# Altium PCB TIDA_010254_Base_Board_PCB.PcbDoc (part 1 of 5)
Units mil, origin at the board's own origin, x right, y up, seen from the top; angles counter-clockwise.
Board outline 3514.38 x 3143.81 mil, 4 copper layers (Top Layer, L2_GND1, L3_PWR1, Bottom Layer), stack 62.715 mil thick; 219 components, 146 nets, 618 pads, 2382 vias.
Unrouted connection lines stored in the file: 2280.
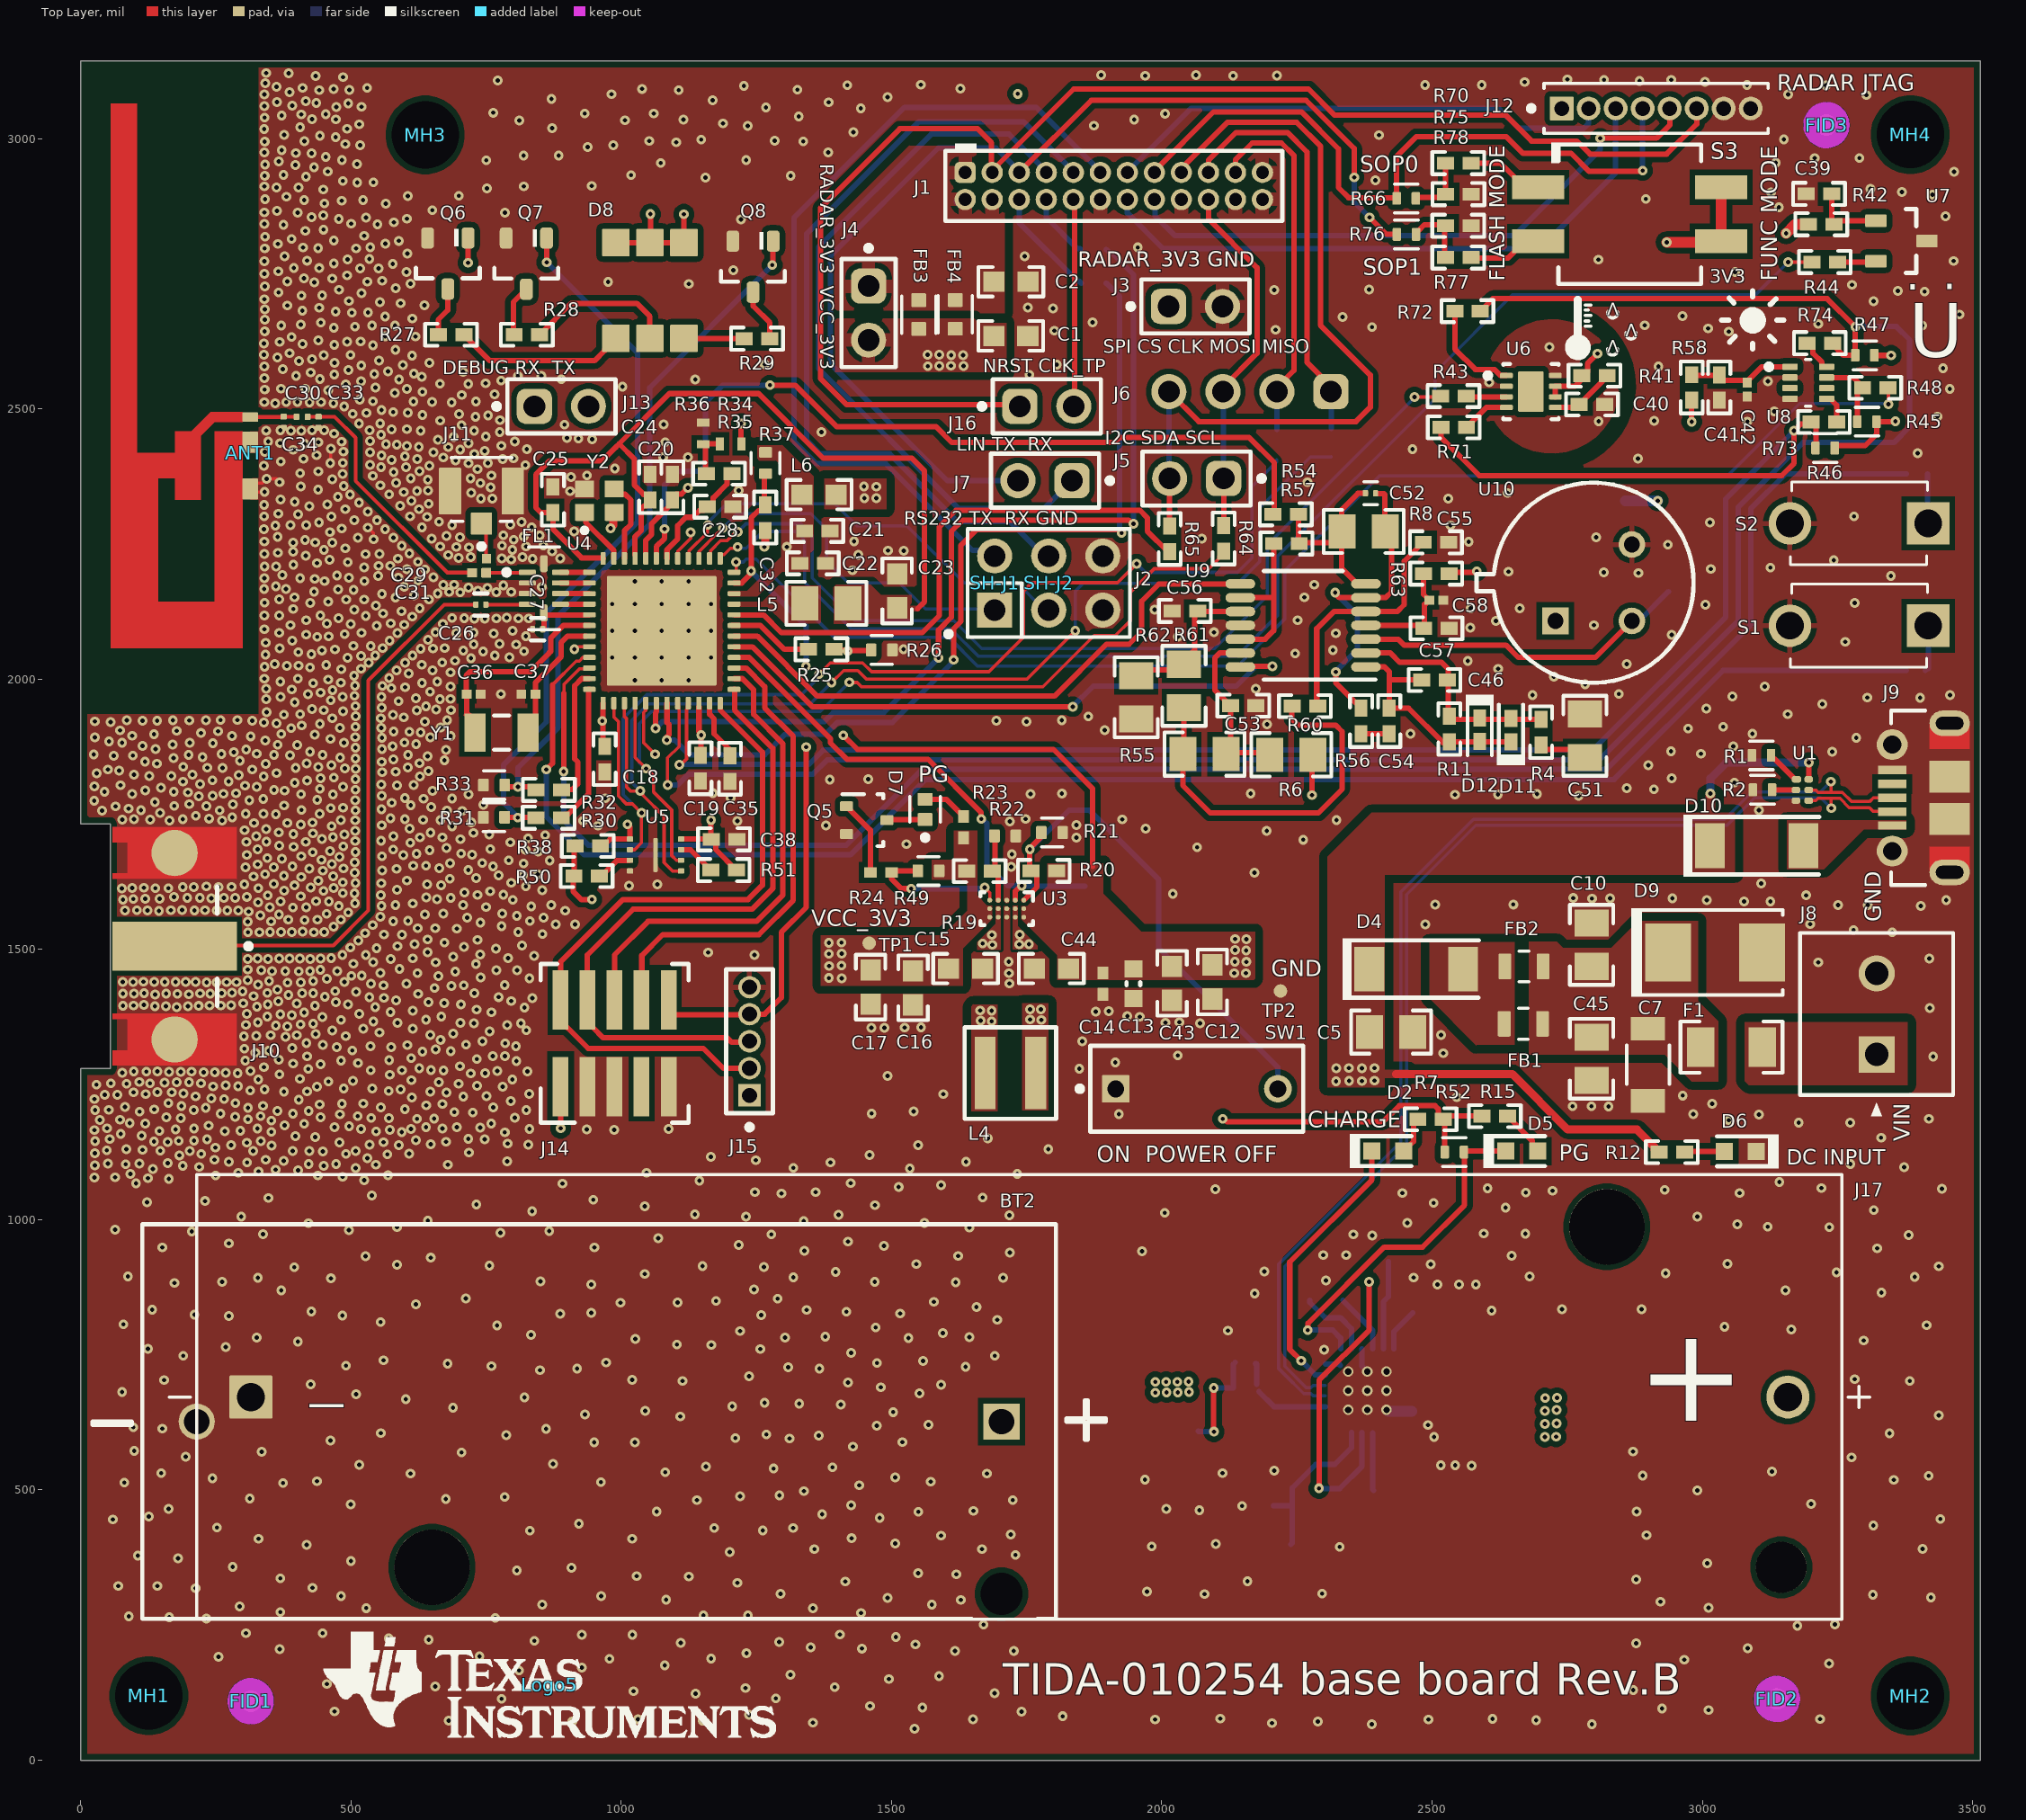
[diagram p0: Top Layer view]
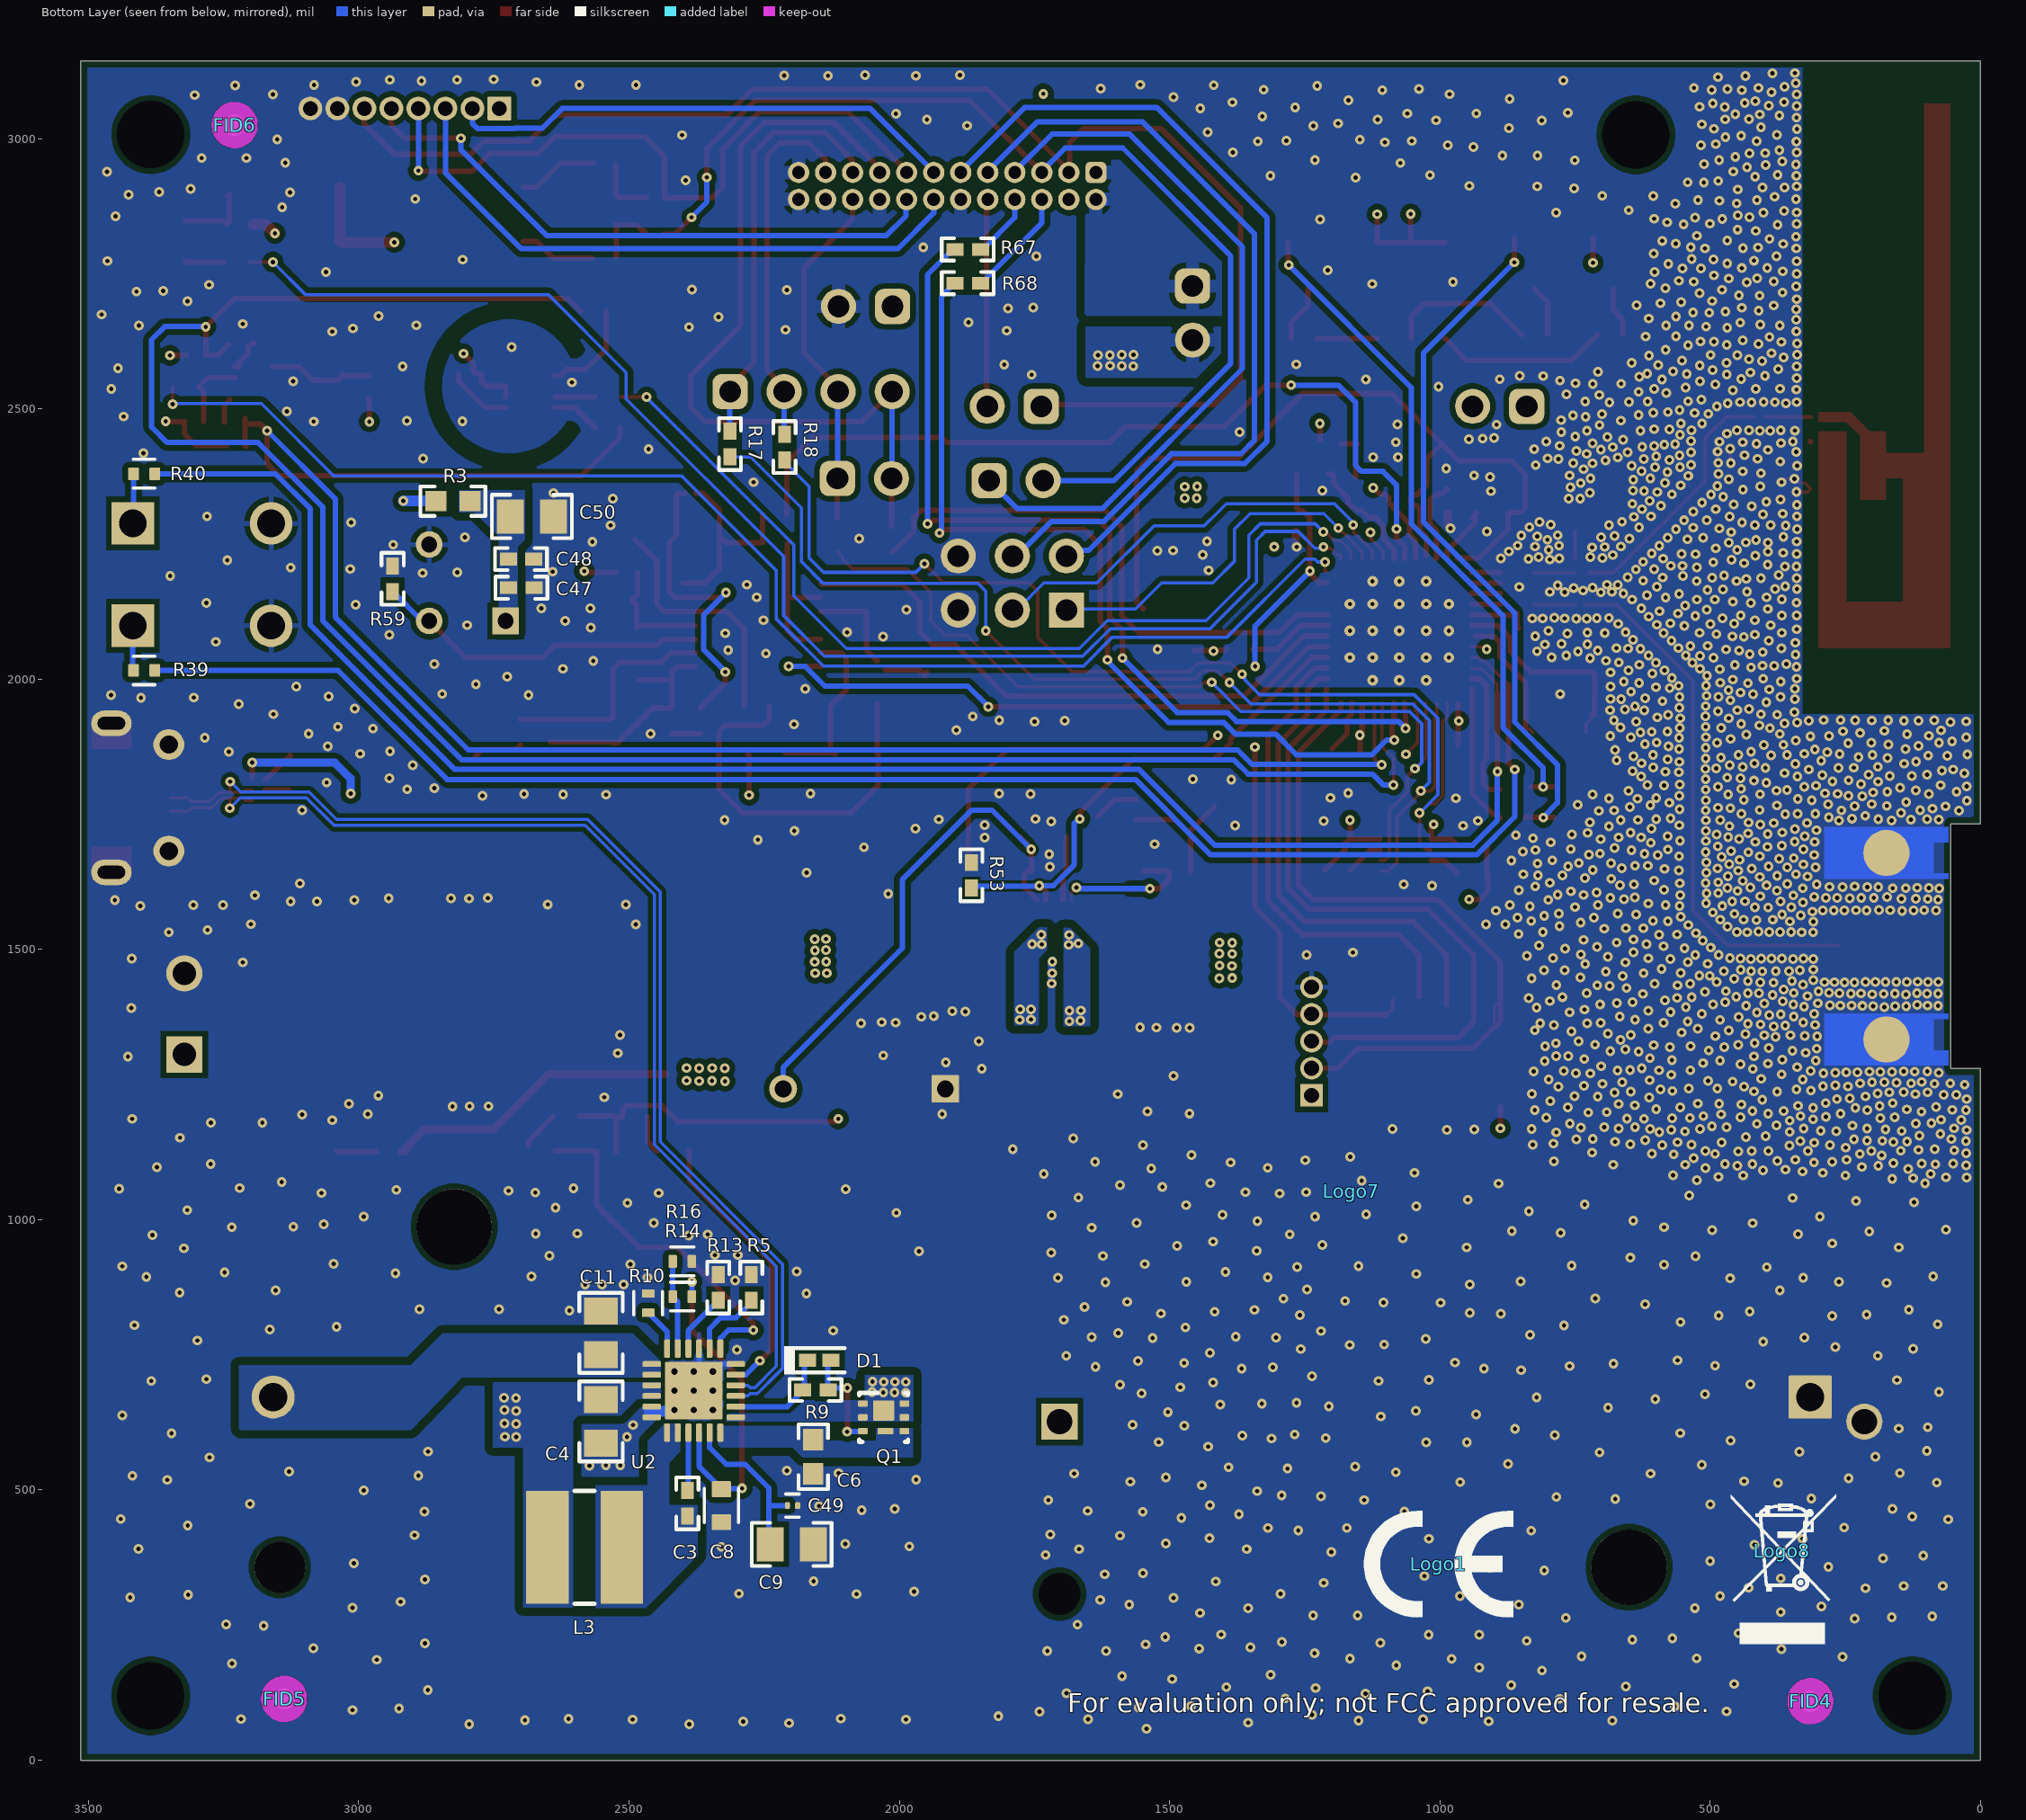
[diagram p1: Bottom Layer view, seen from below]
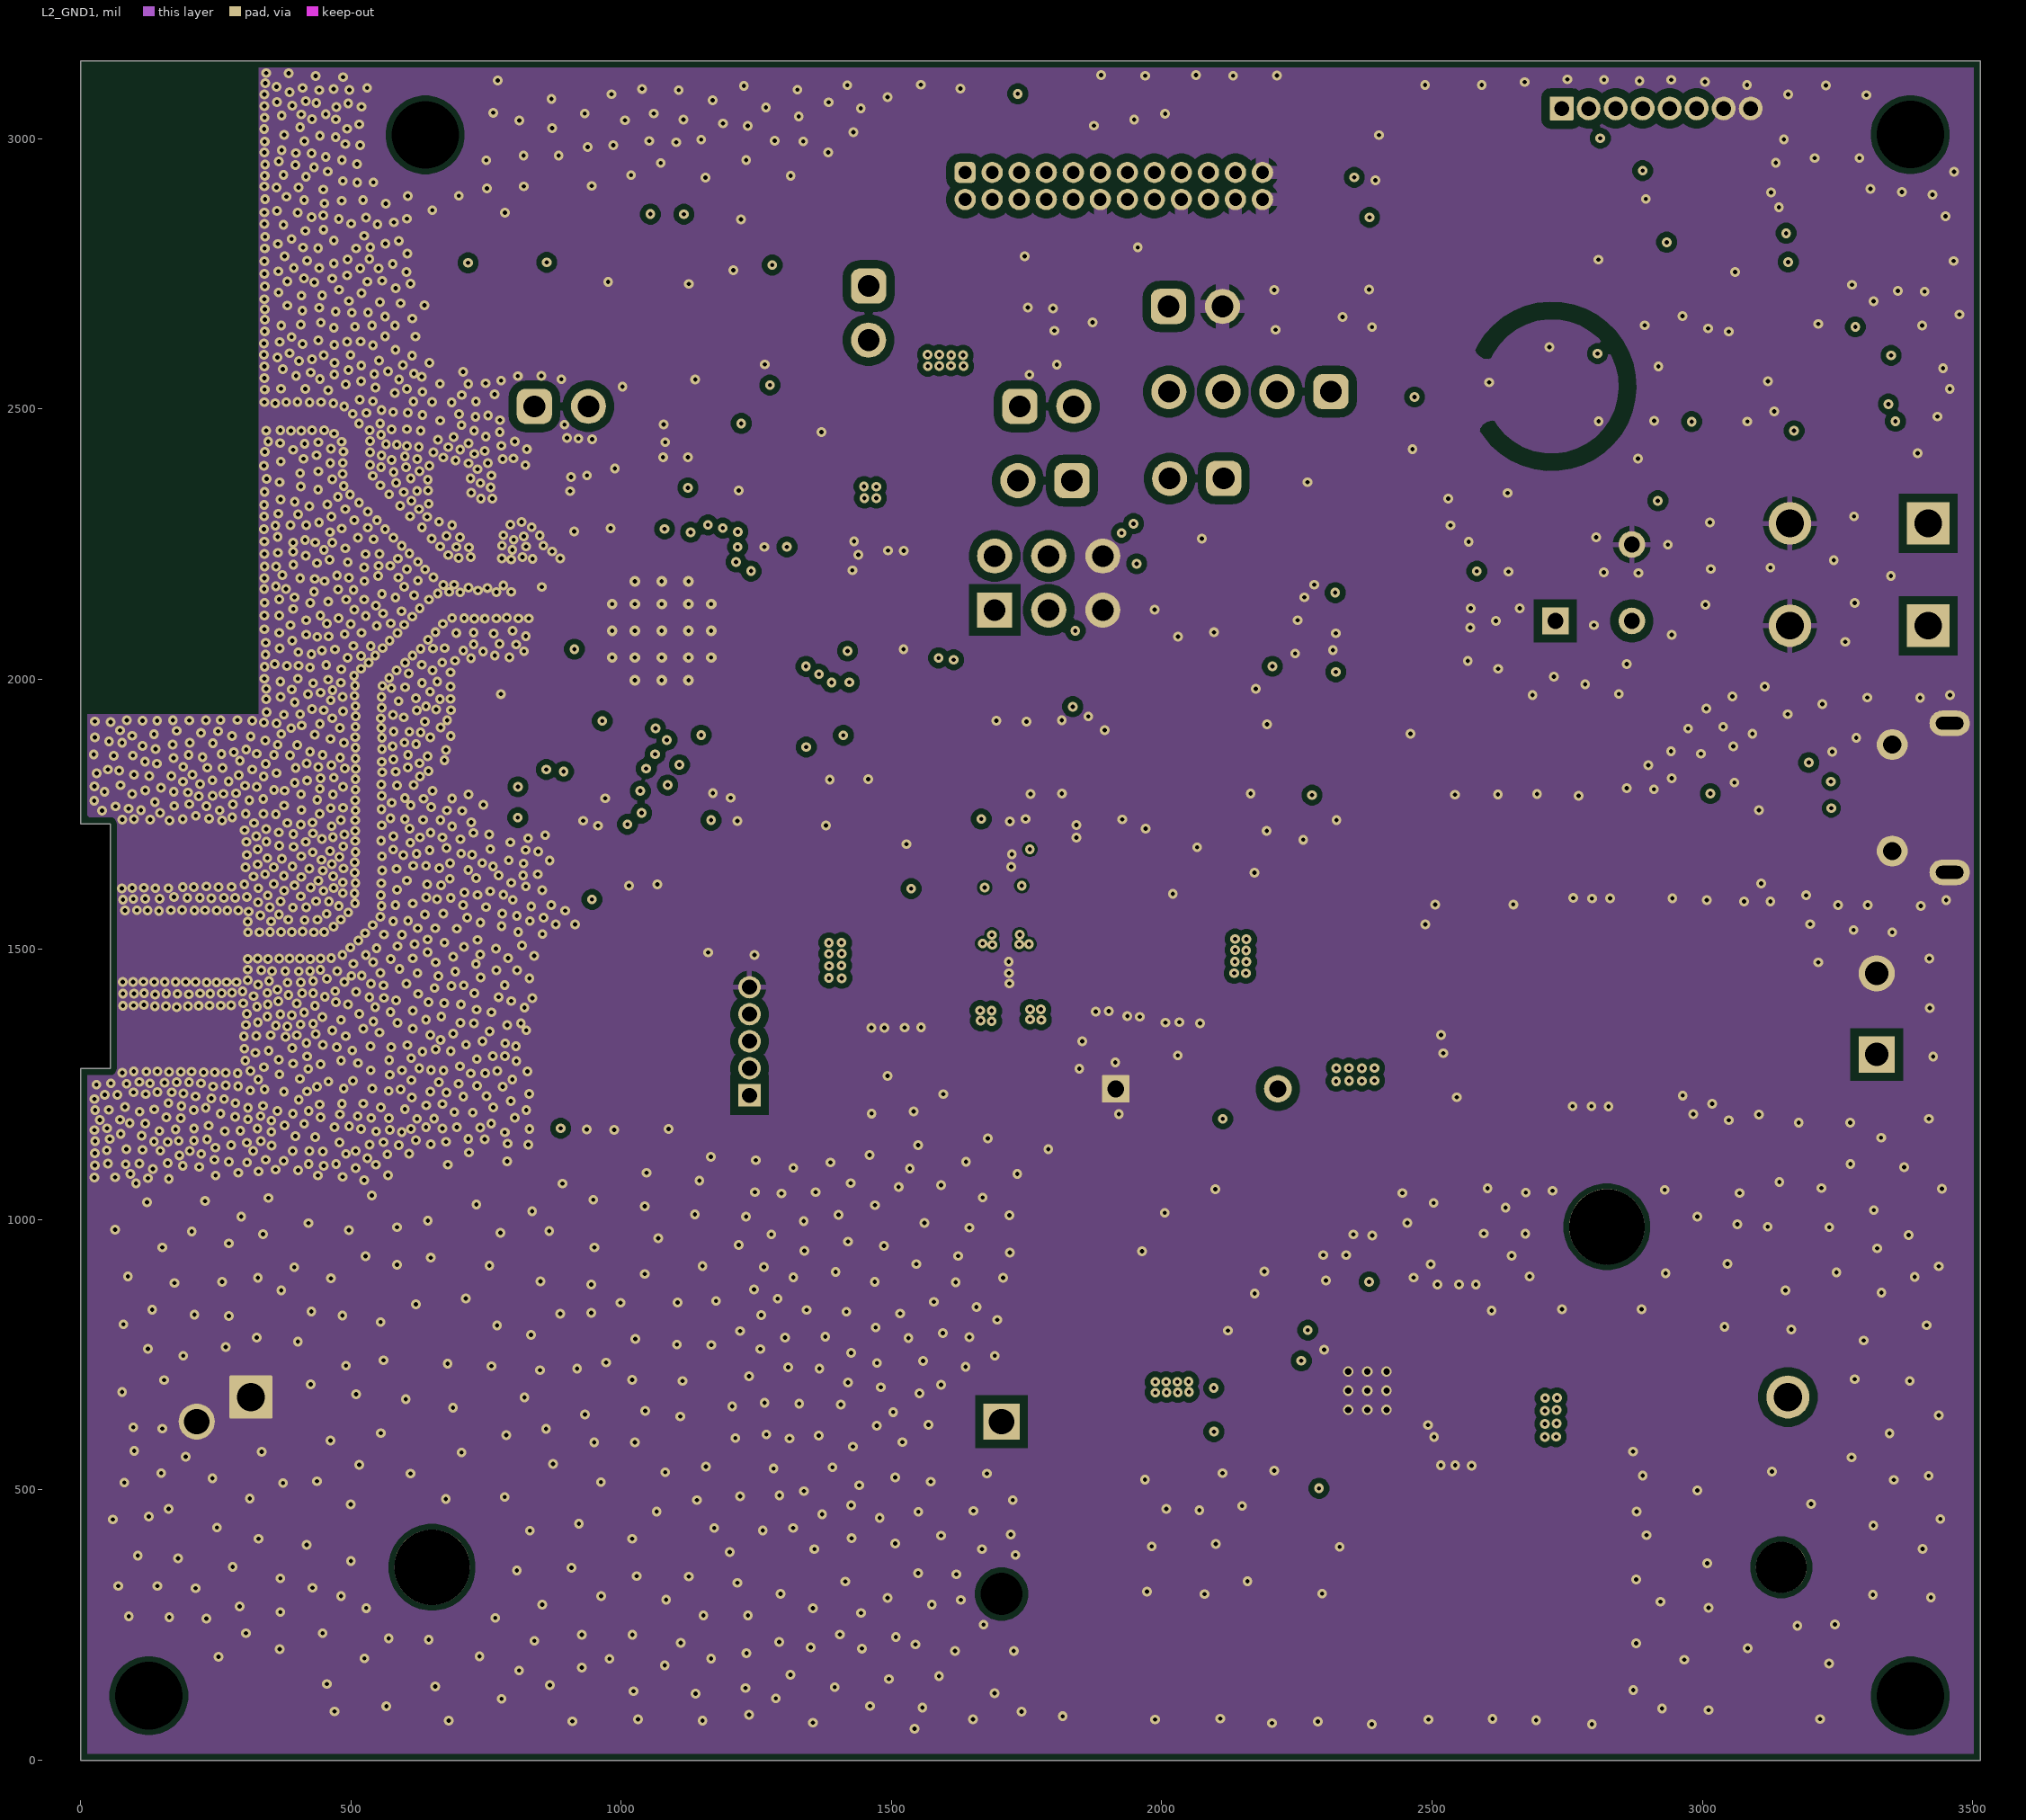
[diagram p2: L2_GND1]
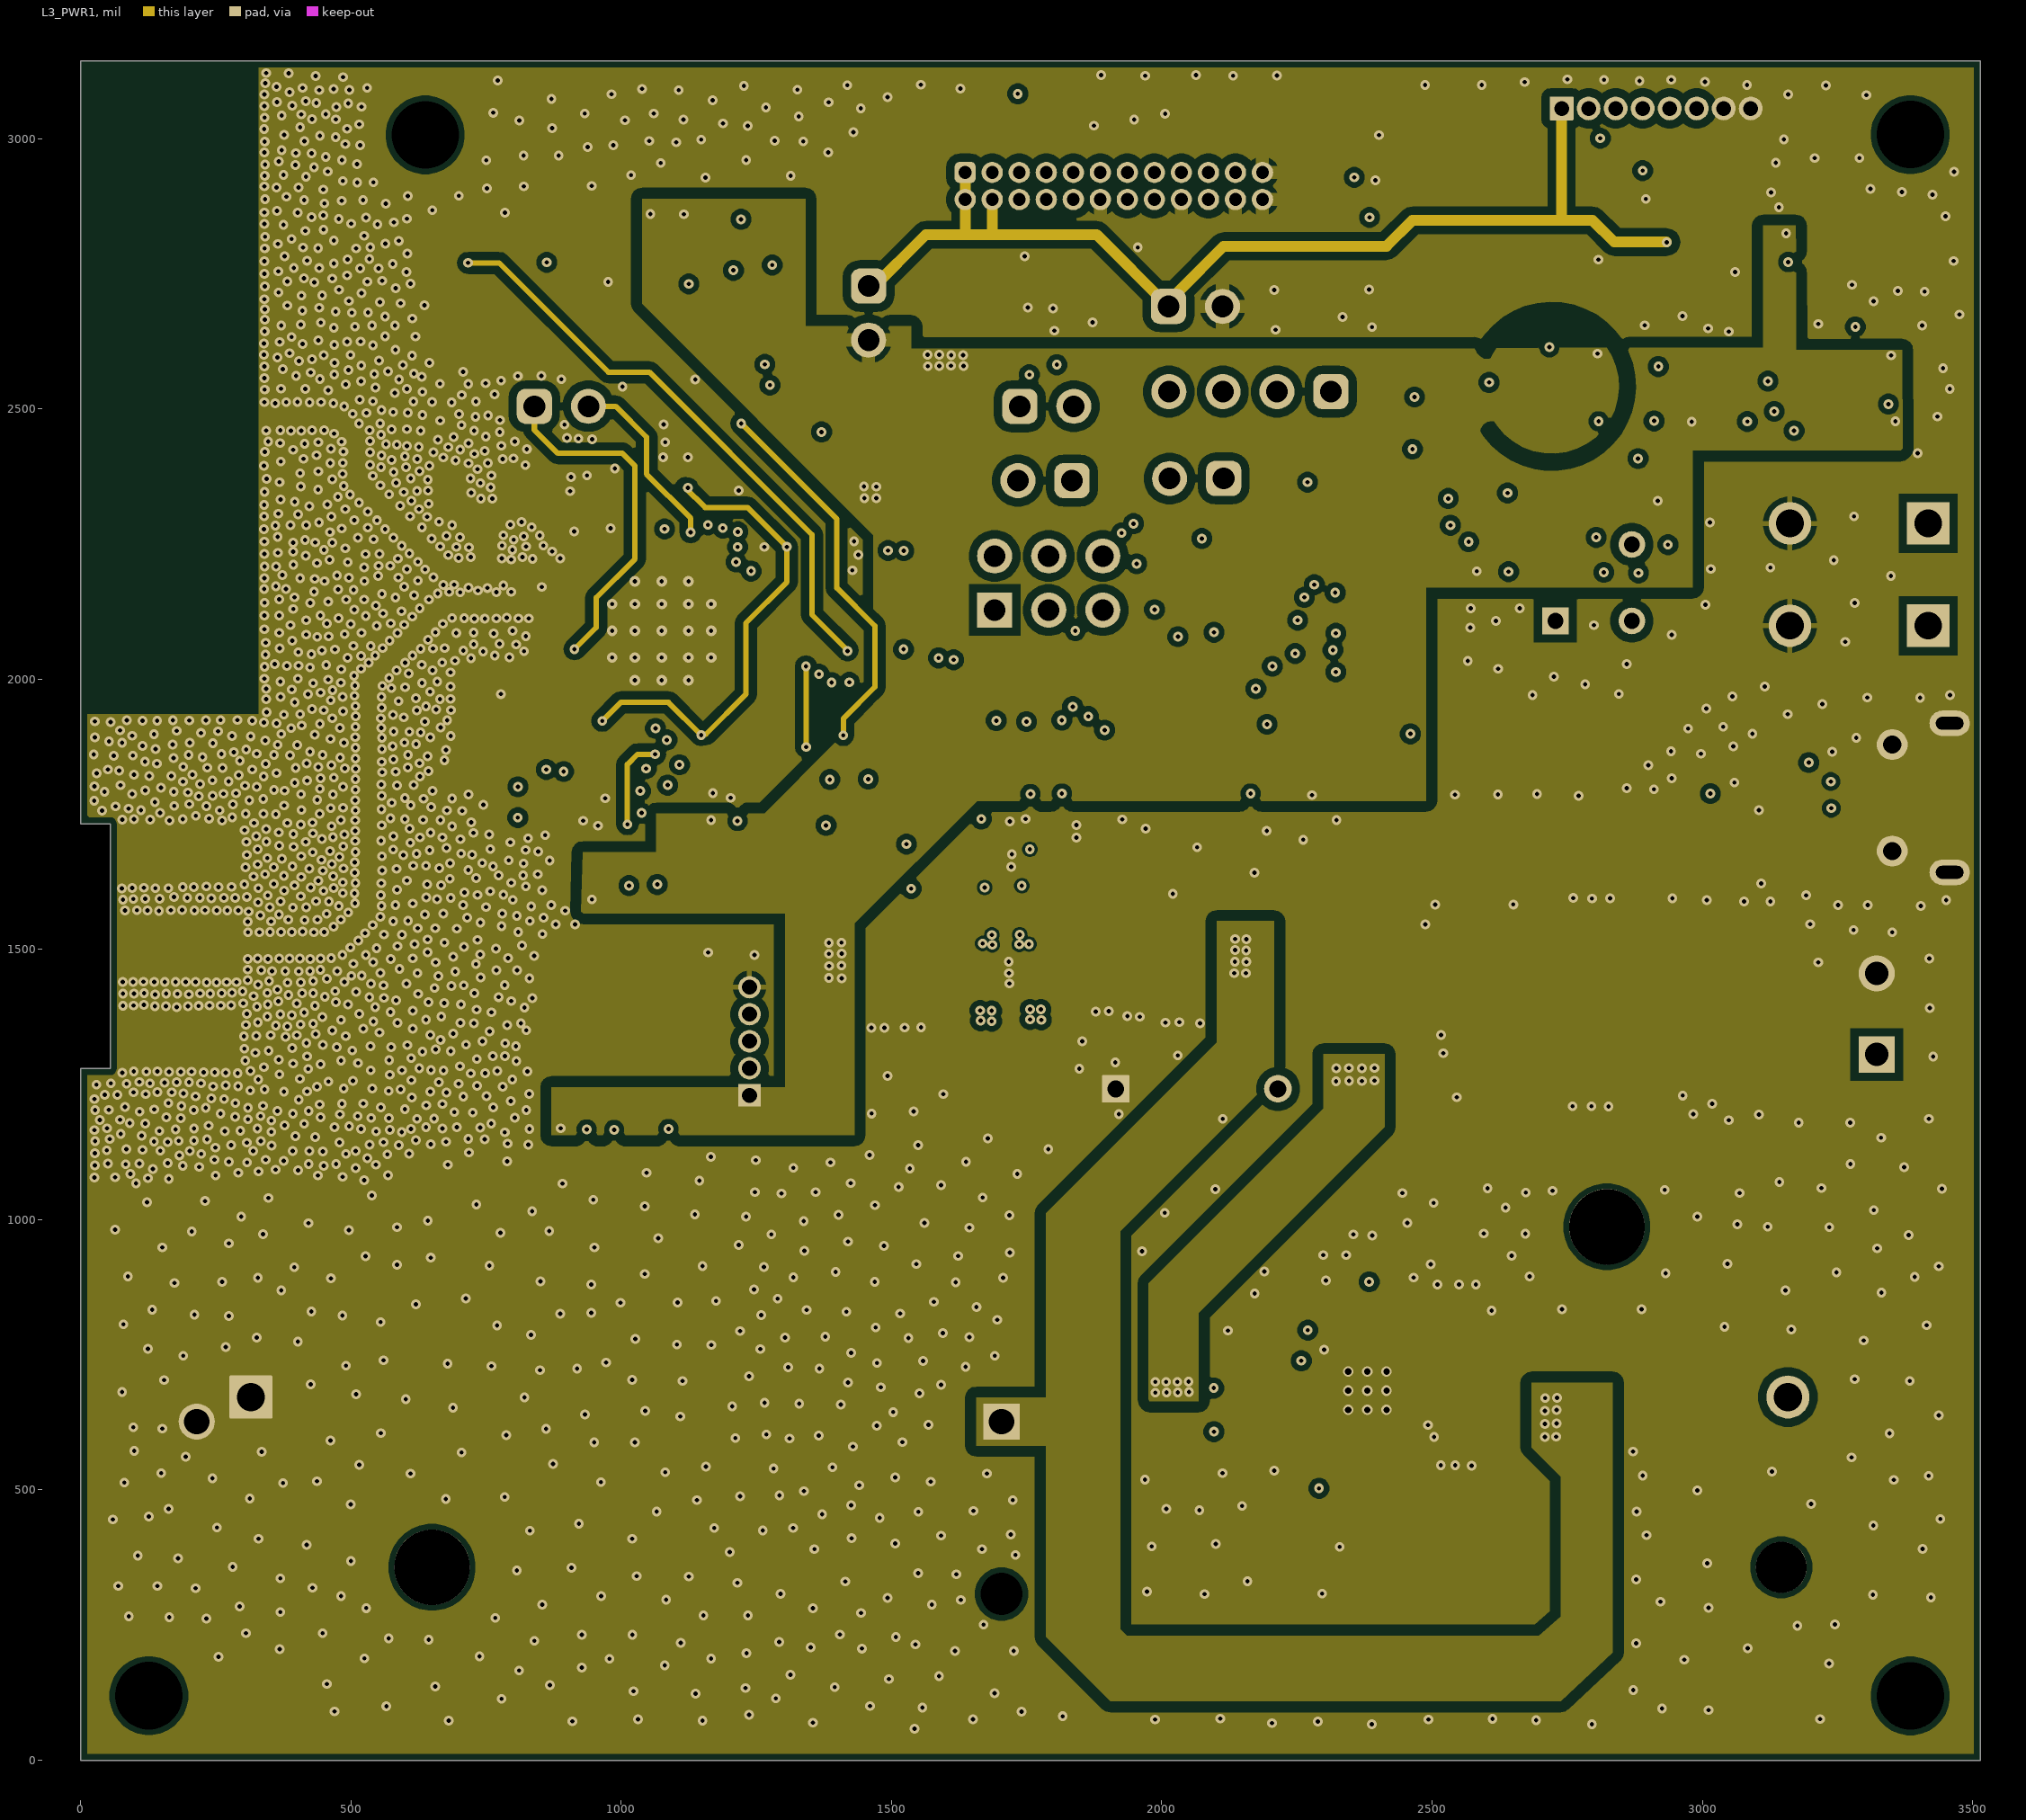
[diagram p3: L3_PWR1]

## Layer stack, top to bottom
Top Solder: solder mask 0.8, Solder Resist, Dk 4
Top Layer: signal copper 1.614
Dielectric 1: core 4.37, FR-4 2116(54%), Dk 4
L2_GND1: signal copper 1.181
Dielectric 2: prepreg 48.385, KB-6160 1.3mm, Dk 4
L3_PWR1: signal copper 1.181
Dielectric 3: prepreg 4.37, FR-4 2116(54%), Dk 4
Bottom Layer: signal copper 1.614
Bottom Solder: solder mask 0.8, Solder Resist, Dk 4

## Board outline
0,0 0,1279.47 54.85,1279.47 54.85,1732.58 -0.03,1732.58 0,3143.81 3514.35,3143.81 3514.35,0

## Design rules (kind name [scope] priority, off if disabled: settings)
AcuteAngle [All] p1 off: minimum=4.50000000000000E+0001 checktracksonly=FALSE
AssemblyTestPointUsage [All] p1: valid=2
BoardOutlineClearance [All] p1: gap=12 ignorepadtopadclearanceinfootprint=FALSE
Clearance Clearance_Keepout [IsKeepOut] p1: gap=0 ignorepadtopadclearanceinfootprint=TRUE
Clearance Clearance_6 [InNet('USB_D_P')] p2: gap=8 ignorepadtopadclearanceinfootprint=TRUE except(5.2: Arc-Arc Arc-Track Arc-SMDPad Arc-THPad Arc-Via Arc-Fill Track-Track Track-SMDPad Track-THPad Track-Via Track-Fill SMDPad-SMDPad SMDPad-THPad SMDPad-Via SMDPad-Fill THPad-THPad THPad-Via THPad-Fill Via-Via Via-Fill Fill-Fill; 10: Poly-Poly)
Clearance Clearance_7 [InNet('USB_D_N')] p3: gap=8 ignorepadtopadclearanceinfootprint=TRUE except(5.2: Arc-Arc Arc-Track Arc-SMDPad Arc-THPad Arc-Via Arc-Fill Track-Track Track-SMDPad Track-THPad Track-Via Track-Fill SMDPad-SMDPad SMDPad-THPad SMDPad-Via SMDPad-Fill THPad-THPad THPad-Via THPad-Fill Via-Via Via-Fill Fill-Fill; 10: Poly-Poly)
Clearance Clearance_2 [InNet('VCC_3V3') And OnLayer('Top Layer') vs InNet('NetL4_2') And OnLayer('Top Layer')] p4: gap=5 ignorepadtopadclearanceinfootprint=TRUE except(0: Text-Hole; 8: Via-Via)
Clearance Clearance_4 [InNet('NetC6_1') And OnLayer('Bottom Layer') vs InNet('NetC5_1') And OnLayer('Bottom Layer')] p5: gap=5 ignorepadtopadclearanceinfootprint=TRUE except(0: Text-Hole)
Clearance Clearance_5 [InNet('ACDRV') And OnLayer('Bottom Layer') vs InNet('NetC5_1') And OnLayer('Bottom Layer')] p6: gap=5 ignorepadtopadclearanceinfootprint=TRUE except(0: Text-Hole)
Clearance [InNet('VDDS') vs InNet('DCDC_SW')] p7: gap=8 ignorepadtopadclearanceinfootprint=TRUE except(0: Text-Hole)
Clearance Clearance_1 [InNet('SYS_POWER') vs InNet('NetL4_1')] p8: gap=5 ignorepadtopadclearanceinfootprint=TRUE except(0: Text-Hole; 8: Via-Via)
Clearance Clearance_8 [InNet('SYS_POWER') vs InNet('NetC11_1')] p9: gap=5 ignorepadtopadclearanceinfootprint=TRUE except(0: Text-Hole; 8: Via-Via)
Clearance Clearance_U3 [WithinRoom('ROOM1')] p10: gap=5 ignorepadtopadclearanceinfootprint=TRUE except(0: Text-Hole; 8: Text-Text)
Clearance Clearance_3 [InComponent('U2')] p11: gap=5 ignorepadtopadclearanceinfootprint=TRUE except(0: Text-Hole)
Clearance "top and bottom" [OnTopLayer or OnBottomLayer] p12: gap=10 ignorepadtopadclearanceinfootprint=TRUE except(8: Arc-Arc Arc-Track Arc-SMDPad Arc-Fill Track-Track Track-SMDPad Track-Fill SMDPad-SMDPad SMDPad-Fill THPad-Fill Via-Fill; 12: Fill-Fill; 15: Poly-Poly)
Clearance "Inner layers" [OnLayer('L2_GND1')] p13: gap=10 ignorepadtopadclearanceinfootprint=FALSE except(8: Arc-Region Track-Region SMDPad-Region THPad-Region Via-Region; 15: Track-Poly THPad-Poly; 20: Poly-Poly)
Clearance "Inner layers_1" [OnLayer('L3_PWR1')] p14: gap=10 ignorepadtopadclearanceinfootprint=FALSE except(8: Arc-Region Track-Region SMDPad-Region THPad-Region Via-Region; 15: Track-Poly THPad-Poly; 20: Poly-Poly)
Clearance Clearance_all [All] p15: gap=10 ignorepadtopadclearanceinfootprint=TRUE except(0: Text-Hole; 15: Poly-Poly)
Clearance Same_net [All] p16: gap=0 ignorepadtopadclearanceinfootprint=TRUE
ComponentClearance ComponentClearance_MatingCon-3D [All vs not InAnyComponent] p1: gap=0 collisioncheckmode=3 verticalgap=0 showdistances=FALSE
ComponentClearance "ComponentClearance_WEE Logo" [InComponent('Logo4')] p2: gap=0 collisioncheckmode=3 verticalgap=0 showdistances=TRUE
ComponentClearance ComponentClearance_Logo [InComponentClass('Logo')] p3: gap=0 collisioncheckmode=3 verticalgap=0 showdistances=TRUE
ComponentClearance "ComponentClearance_Mounting Holes_Fiducial Marks" [InComponentClass('FiducialMark') vs InPadClass('Mounting Holes PADS')] p4: gap=50 collisioncheckmode=3 verticalgap=10 showdistances=TRUE
ComponentClearance [All] p5: gap=10 collisioncheckmode=3 verticalgap=10 showdistances=TRUE
DiffPairsRouting "Schematic Differential Pairs Routing_1" [InNet('USB_D_N')] p1: maxlimit=5.2 minlimit=5.2 mostfreqgap=5.2 toplayer_minwidth=5.8 toplayer_maxwidth=5.8 toplayer_prefwidth=5.8 bottomlayer_minwidth=5.8 bottomlayer_maxwidth=5.8 bottomlayer_prefwidth=5.8 impedanceprofiledriven=TRUE impedanceprofileid={02BDBB83-5519-48F3-A313-F4CD0F9A21A9} impedanceprofilevalue=90.000000 maxuncoupledlength=500
DiffPairsRouting "Schematic Differential Pairs Routing" [InNet('USB_D_P')] p2: maxlimit=5.2 minlimit=5.2 mostfreqgap=5.2 toplayer_minwidth=5.8 toplayer_maxwidth=5.8 toplayer_prefwidth=5.8 bottomlayer_minwidth=5.8 bottomlayer_maxwidth=5.8 bottomlayer_prefwidth=5.8 impedanceprofiledriven=TRUE impedanceprofileid={02BDBB83-5519-48F3-A313-F4CD0F9A21A9} impedanceprofilevalue=90.000000 maxuncoupledlength=500
DiffPairsRouting 90E [InDifferentialPairClass('USB_90ohm')] p3: maxlimit=7.2 minlimit=5 mostfreqgap=7.2 toplayer_mingap=5.2 toplayer_maxgap=5.2 toplayer_prefgap=5.2 toplayer_minwidth=5.8 toplayer_maxwidth=5.8 toplayer_prefwidth=5.8 bottomlayer_mingap=5.2 bottomlayer_maxgap=5.2 bottomlayer_prefgap=5.2 bottomlayer_minwidth=5.8 bottomlayer_maxwidth=5.8 bottomlayer_prefwidth=5.8 impedanceprofiledriven=TRUE impedanceprofileid={02BDBB83-5519-48F3-A313-F4CD0F9A21A9} impedanceprofilevalue=90.000000 maxuncoupledlength=500
FabricationTestPointUsage TestPointUsage [All] p1: valid=2 allowmultiple=FALSE
FabricationTestpoint Testpoint [All] p1: side=3 testpointundercomponent=TRUE minsize=40 maxsize=100 preferedsize=60 minholesize=0 maxholesize=40 preferedholesize=32 testpointgrid=1 allowsidetop=TRUE allowsidebottom=TRUE usegrid=TRUE gridtolerance=0.01
FanoutControl Fanout_LCC [IsLCC] p1: bgadir=Out bgaviamode=Centered fanoutstyle=Auto fanoutdirection=Alternating viagrid=1 // Fanout_LCC (Default Rule)
FanoutControl Fanout_BGA [IsBGA] p2: bgadir=Out bgaviamode=Centered fanoutstyle=Auto fanoutdirection=Alternating viagrid=1 // Fanout_BGA (Default Rule)
FanoutControl Fanout_Default [All] p4: bgadir=Out bgaviamode=Centered fanoutstyle=Auto fanoutdirection=Alternating viagrid=1 // Fanout_Default (Default Rule)
FanoutControl Fanout_Small [(CompPinCount < 5)] p5: bgadir=Out bgaviamode=Centered fanoutstyle=Auto fanoutdirection=OutThenIn viagrid=1 // Fanout_Small (Default Rule)
Height Room_Hieght [WithinRoom('Room_Hieght 1 MM')] p1: minheight=0 maxheight=41.34 prefheight=39.37
HoleSize [All] p1: absolutevalues=TRUE maxlimit=280 minlimit=5.9 maxpercent=80.000 minpercent=20.000
HoleToHoleClearance HoleToHoleClearance_1 [WithinRoom('BGA1')] p1: gap=4 allowstackedmicrovias=FALSE
MinimumAnnularRing MinimumAnnularRing_ThermalPadVias [IsVia and InAnyComponent] p1: minimumring=3.9
MinimumAnnularRing [All] p2: minimumring=3.9
MinimumSolderMaskSliver MinimumSolderMaskSliver_Logo [InComponentClass('Logo') vs InComponentClass('Logo')] p1: minsoldermaskwidth=0.7
MinimumSolderMaskSliver [All] p2: minsoldermaskwidth=3.5
PlaneConnect [All] p1: planeconnectstyle=Relief reliefexpansion=10 reliefentries=4 reliefconductorwidth=10 reliefairgap=10
PolygonConnect [All] p1: connectstyle=Direct reliefconductorwidth=10 reliefentries=4 polygonreliefangle="90 Angle" airgapwidth=10
RoomDefinition ROOM1 [All] p1: confinementstyle=ConfineIn formatcopy=TRUE lockcomponents=FALSE outline 1602.97,1697.35 1608.06,1692.69 1912.56,1692.69 1912.56,1476 1890.41,1455.76 1573.66,1455.76 1573.66,1691.52 1576.85,1694.43
RoutingVias ThermalPadVias [IsVia and InAnyComponent] p1: holewidth=7.87 width=19.68 viastyle="Through Hole" minholewidth=5 minwidth=13 maxholewidth=12.99 maxwidth=23.62
RoutingVias [All] p2: holewidth=12.2 width=22.4 viastyle="Through Hole" minholewidth=5.9 minwidth=14 maxholewidth=20 maxwidth=40
SMDToCorner [All] p1: distance=25000
SilkToBoardRegionClearance [Not ((IsComment or IsDesignator) And (Hide <> 'False')) and not InRegion(1000,500,4000,800)] p1:
SilkToSilkClearance [All] p1: silktosilkclearance=3
SilkToSolderMaskClearance SilkToSolderMaskClearance_OutLine [istrack and InAnyComponent] p1: minsilkscreentomaskgap=0 clearancetoexposedcopper=FALSE
SilkToSolderMaskClearance SilkscreenOverComponentPads [IsPad] p2: minsilkscreentomaskgap=3 clearancetoexposedcopper=FALSE
SolderMaskExpansion [All] p1: expansion=0 istentingtop=FALSE
UnRoutedNet [All] p1: checkbadconnections=TRUE
Width [All] p1: maxlimit=100 minlimit=4 preferedwidth=10 toplayer_prefwidth=6 midlayer1_minwidth=6 midlayer5_minwidth=6 bottomlayer_prefwidth=6 minimp=50.000000 maximp=50.000000 favimp=50.000000
Width Width_50ohm [InNetClass('RF_50ohm')] p2: maxlimit=10 minlimit=6.5 preferedwidth=10 toplayer_minwidth=7 toplayer_maxwidth=7 toplayer_prefwidth=7 bottomlayer_minwidth=7 bottomlayer_maxwidth=7 bottomlayer_prefwidth=7 impedanceprofiledriven=TRUE impedanceprofileid={3C6D6B4B-E20B-4EAB-9CBA-DB8EFE430D68} impedanceprofilevalue=50.000000 minimp=50.000000 maximp=50.000000 favimp=50.000000
12 further rules are at their usual default settings.

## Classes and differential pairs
component class Shunt: SH-J1 SH-J2
net class RF_50ohm: NetANT1_1 NetC26_1 NetC26_2 NetC29_1 NetC29_2 NetC30_1
component class TIDA_010254_Base_Board_Connector: FB3 FB4 J16 P1 P2 R17 R18 R64 R65 R66 R70 R76 R77 R78 S3
component class TIDA_010254_Base_Board_CC1352R: ANT1 C25 C29 C30 C32 C36 C37 C38 D8 FL1 L5 P3 P4 Q6 Q7 Q8 R28 R29 R30 R31 R32 R33 R34 R35 R36 R37 R38 R39 R40 R51 R67 R68 S1 S2 Y2
component class TIDA_010254_Base_Board_Sensors: C50 C51 C52 C53 C54 C55 C57 C58 D11 D12 LOGO1 LOGO2 LOGO3 R41 R42 R43 R45 R46 R47 R48 R54 R55 R56 R57 R58 R59 R60 R61 R62 R63 R71 R72 U6 U7 U8 U9 U10
component class TIDA_010254_Base_Board_DC_Regulators: BT2 C12 D7 L4 Q5 R53 TP1 TP2
component class TIDA_010254_Base_Board_Charger: C45 D1 D4 D5 D6 D9 D10 F1 FB1 FB2 R12 R13 R52
net class LVDS_D: LVDS_D0_LIN_PHY_RX LVDS_D1_XDS_UARTA_RX_CAN_RX LVDS_D2_XDS_UARTA_TX_CAN_TX LVDS_FRCLK_HOST_CLK_TP
net class POWER: PMIC_CLKOUT_LIN_PHY_TX_SOP1 REG_PG
net class Regions: GND
component class Logo: Logo5
component class FiducialMark: FID1 FID2 FID3 FID4 FID5 FID6
component class TIDA_010254_Base_Board_Hardware: FID1 FID2 FID3 FID4 FID5 FID6 Logo1 Logo5 Logo7 Logo8 MH1 MH2 MH3 MH4 SH-J1 SH-J2 ZZ1 ZZ2 ZZ3 ZZ4 ZZ5
component class AssemblyNote: ZZ1 ZZ2 ZZ3 ZZ4 ZZ5
component class Header: J16 LD2 LD4 SW2
differential pair USB_DP: +USB_D_P -USB_D_N

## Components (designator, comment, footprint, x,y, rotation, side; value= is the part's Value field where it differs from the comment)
ANT1 "Inverted F Antenna" 0-MFG 192.2,2560.93 r90 top
BT2 "1051" Keystone_1051 959.07,626.51 r180 top
C1 "GRM188Z71A106MA73D" 0603 1720.65,2635.07 r0 top value=10uF
C2 "GRM188Z71A106MA73D" 0603 1720.81,2734.97 r0 top value=10uF
C3 "GRM155R71E473KA88D" 0402 2391.91,475.34 r90 bottom value=0.047uF
C4 "GRM21BR71A106KA73L" 0805_HV 2551.82,626.78 r270 bottom value=10uF
C5 "GRM21BR61E106KA73L" 0805_HV 2424.17,1347.14 r0 top value=10uF
C6 "C1608X7R1V105K080AC" 0603 2159.2,561.48 r270 bottom value=1uF
C7 "GRM31CR61A476KE15L" 1206_180 2899.43,1286.8 r270 top value=47uF
C8 "GRM188R61C475KE11D" FP-GRM188R61C475KE11D_0603-MFG 2329.1,470.95 r270 bottom value=4.7µF
C9 "GRM21BR61E106KA73L" 0805_HV 2199.08,399.42 r180 bottom value=10uF
C10 "GRM21BR61E106KA73L" 0805_HV 2794.94,1508.57 r90 top value=10uF
C11 "GRM21BR71A106KA73L" 0805_HV 2551.82,790.64 r90 bottom value=10uF
C12 "GRM188Z71A106MA73D" 0603 2093.56,1439.84 r270 top value=10uF
C13 "GRM188R71C474KA88D" 0603L 1947.37,1436.62 r270 top value=0.47uF
C14 "GRM1555C1H471JA01D" 0402L 1890.95,1436.62 r270 top value=470pF
C15 "GRM188R60J476ME15D" 0603 1637.02,1464.57 r0 top value=47uF
C16 "GRM188R60J476ME15D" 0603 1539.77,1428.99 r270 top value=47uF
C17 "GRM188R60J476ME15D" 0603 1461.06,1430.27 r270 top value=47uF
C18 "GRM155R71E104KE14D" 0402 969.23,1851.98 r270 top value=0.1uF
C19 "GRM155R71E104KE14D" 0402 1146.52,1835.28 r270 top value=0.1uF
C20 "GRM155R71E104KE14D" 0402 1094.57,2355.13 r90 top value=0.1uF
C21 "GRM155R71E104KE14D" 0402 1362.82,2274.3 r0 top value=0.1uF
C22 "GRM155R71E104KE14D" 0402 1354.38,2214.29 r0 top value=0.1uF
C23 "GRM188R60J226MEA0D" 0603 1510.18,2163.32 r90 top value=22uF
C24 "GRM155R71E104KE14D" 0402 1053.6,2355.29 r90 top value=0.1uF
C25 "GRM155R71E104KE14D" 0402 873.56,2331.91 r90 top value=0.1uF
C26 "GRM033R60J104KE19D" FP-GRM033R60J104KE19D_0201-MFG 740.22,2137.95 r0 top
C27 "GRM033R60J104KE19D" FP-GRM033R60J104KE19D_0201-MFG 845.38,2092.43 r0 top
C28 "GRM155R70J105KA12D" 0402 1183.07,2319.2 r0 top value=1uF
C29 "GRM0335C1H120JA01D" 0201 750.54,2210.03 r270 top value=12pF
C30 "1.2pF" FP-GRM0335C1H1R2BA01D_0201-MFG 409.53,2485.23 r180 top
C31 "GRM0335C1H120JA01D" 0201 737.21,2196.88 r180 top value=12pF
C32 "GRM155R71E104KE14D" 0402 1266.25,2298.74 r270 top value=0.1uF
C33 "1.2pF" FP-GRM0335C1H1R2BA01D_0201-MFG 440.03,2475.2 r270 top
C34 "1.2pF" FP-GRM0335C1H1R2BA01D_0201-MFG 375.46,2475.25 r270 top
C35 "GRM155R70J105KA12D" 0402 1201.04,1834.44 r270 top value=1uF
C36 "GRM0335C1H120JA01D" 0201 726.94,1972.46 r0 top value=12pF
C37 "GRM0335C1H120JA01D" 0201 828.15,1972.46 r180 top value=12pF
C38 "GRM155R71E104KE14D" 0402 1190.21,1703.61 r0 top value=0.1uF
C39 "GRM155R71E104KE14D" 0402 3215.93,2897.74 r180 top value=0.1uF
C40 "GRM155R71E104KE14D" 0402 2795.73,2508.25 r0 top value=0.1uF
C41 "GRM155R71E104KE14D" 0402 3031.27,2539.48 r270 top value=0.1uF
C42 "GRM033R61A103KA01D" 0201 3082.77,2535.76 r270 top value=0.01uF
C43 "GRM188Z71A106MA73D" 0603 2018.9,1437.3 r270 top value=10uF
C44 "GRM188Z71A106MA73D" 0603 1795.71,1464.53 r180 top value=10uF
C45 "GRM21BR61E106KA73L" 0805_HV 2794.94,1297.89 r270 top value=10uF
C46 "GRM155R71H103KA88D" 0402 2504.49,1998.42 r0 top value=0.01uF
C47 "GRM1555C1H120JA01D" 0402 2699.57,2222.19 r180 bottom value=12pF
C48 "GRM155R71E104KE14D" 0402 2698.98,2169.17 r180 bottom value=0.1uF
C49 "GRM033R61E102KA01D" FP-GRM033R61E102KA01D_0201-MFG 2197.37,471.19 r0 bottom value=1nF
C50 "GRM21BR71A106KA73L" 0805_HV 2679.75,2300.96 r180 bottom value=10uF
C51 "C2012X5R1A336M125AC" 0805_HV 2782.83,1895.26 r90 top value=33uF
C52 "GRM033R61E102KA01D" FP-GRM033R61E102KA01D_0201-MFG 2386.26,2343.84 r180 top value=1nF
C53 "GRM155R71H104ME14D" 0402 2150.61,1950.95 r0 top value=0.1uF
C54 "C1005X5R1A335K050BC" 0402 2420.67,1922.6 r90 top value=3.3uF
C55 "GRM155R71H104ME14D" 0402 2507.35,2253.15 r0 top value=0.1uF
C56 "GRM155R71H104ME14D" 0402 2042.7,2126.21 r180 top value=0.1uF
C57 "GRM155R71E104KE14D" 0402 2508.22,2094.16 r0 top value=0.1uF
C58 "GRM033R61A103KA01D" 0201 2507.81,2146.14 r0 top value=0.01uF
D1 "ZLLS350TA" SOD-523 2148.36,739.82 r180 bottom value=40V
D2 "LTST-C190GKT" LED_LTST-C190 2418.34,1126.97 r180 top value=Green
D4 "PMEG3020EP,115" SOD-128 2470.5,1463.73 r0 top value=30V
D5 "LTST-C190GKT" LED_LTST-C190 2665.55,1126.97 r180 top value=Green
D6 "LTST-C190GKT" LED_LTST-C190 3070.32,1126.58 r0 top value=Green
D7 "VLMY1500-GS08" FP-VLMY1500-GS08_0402-MFG 1562.16,1759.1 r90 top
D8 "LTST-G563EGBW" G563EGBW 1053.01,2719.01 r90 top value=Rgb
D9 "SZP6SMB6.8AT3G" SMB 3023.54,1494.38 r0 top value=5.8V
D10 "PMEG3020EP,115" SOD-128 3100.65,1691.93 r0 top value=30V
D11 "1N4148X-TP" SOD-523 2645.81,1905.73 r90 top value=75V
D12 "1N4148X-TP" SOD-523 2588.17,1906.34 r270 top value=75V
F1 "32V, 5A" 1206 3053.86,1319.24 r0 top
FB1 "BLM21PG300SN1D" FP-BLM21PG300SN1D_0805-MFG 2668.94,1362.4 r180 top
FB2 "BLM21PG300SN1D" FP-BLM21PG300SN1D_0805-MFG 2670.16,1468.61 r180 top
FB3 "BLM18KG121TN1D" FP-BLM18KG121TN1D_0603-MFG 1550.22,2674.56 r90 top
FB4 "BLM18KG121TN1D" FP-BLM18KG121TN1D_0603-MFG 1617.85,2674.97 r90 top
FID1 "Fiducial" Fiducial10-20 314.8,109.23 r90 top
FID2 "Fiducial" Fiducial10-20 3137.89,113.48 r90 top
FID3 "Fiducial" Fiducial10-20 3229.63,3025 r90 top
FID4 "Fiducial" Fiducial10-20 314.8,109.23 r90 bottom
FID5 "Fiducial" Fiducial10-20 3137.89,113.48 r90 bottom
FID6 "Fiducial" Fiducial10-20 3229.63,3025 r90 bottom
FL1 "0900PC15A0036" FP-0900PC15A0036_0805-MFG 856.89,2168.19 r270 top locked
J1 "LPPB122CFFN-RC" Sullins_LPPB122CFFN 1911.28,2912.4 r0 top locked
J2 "TSW-103-07-G-D" TSW-103-07-G-D 1790.81,2177.82 r0 top
J3 "TSW-102-07-G-S" TSW-102-07-G-S 2062.34,2689.57 r0 top
J4 "TSW-102-07-G-S" TSW-102-07-G-S 1457.5,2677.24 r270 top
J5 "TSW-102-07-G-S" TSW-102-07-G-S 2064.44,2371.16 r180 top
J6 "TSW-104-07-G-S" TSW-104-07-G-S 2163.01,2531.94 r180 top
J7 "TSW-102-07-G-S" TSW-102-07-G-S 1783.87,2367.31 r180 top
J8 "1727010" PhoenixConact_1727010 3322.4,1380.63 r90 top
J9 "105017-0001" CONN_105017-0001 3404.41,1780.51 r90 top
J10 "0732511150" FP-0732511150_CONN_RF_JACK-MFG -35.21,1505.91 r0 top
J11 "1909763-1" "FP-1909763-1_SMT_JACK _CONN-MFG" 741.39,2350.89 r0 top
J12 "851-43-008-10-021000" FP-851-43-008-10-021000_HDR8-MFG 2914.56,3055.87 r0 top
J13 "TSW-102-07-G-S" TSW-102-07-G-S 889.29,2504.8 r0 top
J14 "FTSH-105-01-F-DV-K" Samtec_FTSH-105-01-x-DV-K 987.62,1326.45 r90 top
J15 "851-87-005-10-001101" PRECI-DIP_851-87-005-10-001101 1237.27,1330.13 r90 top
J16 "TSW-102-07-G-S" TSW-102-07-G-S 1787.33,2504.8 r0 top
J17 "1043P" FP-1043P_BATT_HOLDER_18650-MFG 1736.64,671.9 r0 top
L3 "74408943010" WE-SPC_4838 2582.15,393.99 r0 bottom value=1uH
L4 "XFL4015-471MEC" XFL4015 1720,1271.08 r180 top value=470nH
L5 "MLZ2012N6R8LT000" 0805_HV 1379.41,2140.26 r0 top value=6.8uH
L6 "BLM18HE152SN1D" 0603 1365.95,2341.39 r180 top value="1500 ohm"
Logo1 "CE Mark" CE_Mark_5mm 1002.45,362.93 r180 bottom
Logo5 "Texas Instruments" TI_Stacked_Overlay_Small 867.91,139.13 r0 top
Logo7 "FCC disclaimer" FCC_disclaimer 1163.87,1053.04 r180 bottom
Logo8 "WEEE logo" WEEE_Minimum 366.47,387.21 r180 bottom
MH1 "MTG_NoPads" NPTH125mil 125.95,119.47 r0 top
MH2 "MTG_NoPads" NPTH125mil 3384.76,118.94 r0 top
MH3 "MTG_NoPads" NPTH125mil 637.33,3006.81 r0 top
MH4 "MTG_NoPads" NPTH125mil 3384.76,3007.5 r0 top
Q1 "CSD17571Q2" DQK0006C 2028.96,634.29 r180 bottom value=30V
Q5 "BSS123W-7-F" SOT-323 1454.09,1739.21 r0 top value=100V
Q6 "MMBT2222ALT1G" SOT-23 679.07,2768.96 r270 top value="40 V"
Q7 "MMBT2222ALT1G" SOT-23 824.44,2768.67 r270 top value="40 V"
Q8 "MMBT2222ALT1G" SOT-23 1243.76,2763.13 r270 top value="40 V"
R1 "10K" FP-CRCW040210K0FKEDC_0402-MFG 3109.38,1859.06 r0 top value=10k
R2 "10K" FP-CRCW040210K0FKEDC_0402-MFG 3111.27,1795.39 r0 top value=10k
R3 "CRCW0603332KFKEA" 0603 2825.72,2329.36 r0 bottom value=332k
R4 "CRCW04026K81FKED" 0402 2701.6,1901.87 r90 top value=6.81k
R5 "CRCW0402150RFKED" 0402 2273.73,874.39 r270 bottom value=150
R6 "RMCF0805JT15M0" 0805_HV 2239.51,1860.2 r0 top value=15Meg
R7 "CRCW04022K21FKED" 0402 2497.35,1185.77 r180 top value=2.21k
R8 "RMCF0805JT15M0" 0805_HV 2373.7,2273.38 r180 top value=15Meg
R9 "RC0402JR-070RL" 0402 2155.05,685.13 r0 bottom value=0
R10 "10K" FP-CRCW040210K0FKEDC_0402-MFG 2464.41,845.74 r270 bottom value=10k
R11 "RC0402FR-071M5L" 0402 2531.99,1907.7 r270 top value=1.50Meg
R12 "CRCW04022K21FKED" 0402 2943.49,1125.11 r0 top value=2.21k
R13 "ERJ-2RKF2200X" 0402 2334.9,874.39 r270 bottom value=220
R14 "10K" FP-CRCW040210K0FKEDC_0402-MFG 2401.39,857.67 r180 bottom value=10k
R15 "CRCW04022K21FKED" 0402 2616.07,1191.59 r180 top value=2.21k
R16 "10K" FP-CRCW040210K0FKEDC_0402-MFG 2401.39,922.83 r0 bottom value=10k
R17 "RC0402JR-070RL" 0402 2313.29,2434.98 r270 bottom value=0
R18 "RC0402JR-070RL" 0402 2212.23,2429.45 r270 bottom value=0
R19 "CRCW0402511KFKED" 0402 1662.96,1644.77 r180 top value=511k
R20 "CRCW0402200KFKED" 0402 1781.75,1645.25 r0 top value=200k
R21 "100K" FP-RC0402JR-07100KL_0402-MFG 1796.89,1716.3 r0 top value=100k
R22 "RC0402FR-0791KL" RC0402 1710.26,1709.88 r180 top value=91.0k
R23 "ERJ-2GEJ511X" 0402L 1633.43,1726.11 r270 top value=510
R24 "ERJ-2GEJ511X" 0402L 1480.53,1642.32 r180 top value=510
R25 "CRCW04024K70JNED" 0402 1370.14,2055.14 r0 top value=4.7k
R26 "100K" FP-RC0402JR-07100KL_0402-MFG 1481.89,2054.02 r0 top value=100k
R27 "CRCW04022K21FKED" 0402 685.17,2637.27 r0 top value=2.21k
R28 "CRCW04022K21FKED" 0402 825.46,2637.27 r0 top value=2.21k
R29 "CRCW04022K21FKED" 0402 1251.21,2629.86 r180 top value=2.21k
R30 "CRCW04024K70JNED" 0402 865.54,1743.55 r180 top value=4.7k
R31 "100K" FP-RC0402JR-07100KL_0402-MFG 764.51,1744.49 r180 top value=100k
R32 "CRCW04024K70JNED" 0402 866,1795.24 r180 top value=4.7k
R33 "100K" FP-RC0402JR-07100KL_0402-MFG 764.74,1804.12 r180 top value=100k
R34 "CRCW040268K1FKED" 0402S 1202.65,2435.42 r0 top value=68.1k
R35 "CRCW04022K21FKED" 0402 1181,2380.17 r180 top value=2.21k
R36 "CRCW040268K1FKED" 0402S 1151.61,2454.44 r270 top value=68.1k
R37 "100K" FP-RC0402JR-07100KL_0402-MFG 1266.92,2399.87 r90 top value=100k
R38 "CRCW04022K20JNED" 0402 937.94,1691.4 r180 top value=2.2k
R39 "RC0402JR-13100RL" FP-RC0402JR-13100RL_0402-MFG 3396.91,2016.26 r0 bottom value=100
R40 "RC0402JR-13100RL" FP-RC0402JR-13100RL_0402-MFG 3396.91,2379.92 r0 bottom value=100
R41 "RC0402JR-070RL" 0402 2800.34,2561.62 r180 top value=0
R42 "RC0402JR-070RL" 0402 3219.91,2841.49 r180 top value=0
R43 "RC0402JR-070RL" 0402 2539.6,2523.63 r180 top value=0
R44 "RC0402JR-070RL" 0402 3226.43,2771.61 r0 top value=0
R45 "10K" FP-CRCW040210K0FKEDC_0402-MFG 3304.4,2476.3 r0 top value=10k
R46 "10K" FP-CRCW040210K0FKEDC_0402-MFG 3227.06,2427.57 r0 top value=10k
R47 "10K" FP-CRCW040210K0FKEDC_0402-MFG 3300.44,2599.26 r0 top value=10k
R48 "RC0402JR-070RL" 0402 3319.94,2539 r0 top value=0
R49 "100K" FP-RC0402JR-07100KL_0402-MFG 1568.35,1645.25 r180 top value=100k
R50 "CRCW04022K20JNED" 0402 936.13,1635.68 r180 top value=2.2k
R51 "CRCW04022K20JNED" 0402 1189.43,1646.88 r0 top value=2.2k
R52 "10K" FP-CRCW040210K0FKEDC_0402-MFG 2541.24,1125.11 r0 top value=10k
R53 "RMCF0402FT1M00" 0402 1866.5,1637.05 r270 bottom value=1.00Meg
R54 "RC0402JR-070RL" 0402 2229.33,2305.11 r180 top value=0
R55 "RMCF0805JT15M0" 0805_HV 2078.91,1861.26 r0 top value=15Meg
R56 "CRCW040268K1FKED" 0402 2368.7,1922.6 r90 top value=68.1k
R57 "RC0402JR-070RL" 0402 2230.57,2250.92 r180 top value=0
R58 "RC0402JR-070RL" 0402 2980.19,2539.54 r90 top value=0
R59 "CRCW04021M30FKED" 0402 2937.32,2185.64 r270 bottom value=1.30Meg
R60 "RC0402JR-070RL" 0402 2264.8,1950.1 r180 top value=0
R61 "RMCF0805JT15M0" 0805_HV 2041.05,1987.51 r270 top value=15Meg
R62 "RMCF0805JT15M0" 0805_HV 1952.66,1966.24 r90 top value=15Meg
R63 "RC0402JR-070RL" 0402 2507.6,2195.35 r180 top value=0
R64 "RC0402JR-070RL" 0402 2114.33,2260.15 r270 top value=0
R65 "RC0402JR-070RL" 0402 2014.57,2259.47 r270 top value=0
R66 "10K" FP-CRCW040210K0FKEDC_0402-MFG 2452.23,2889.44 r180 top value=10k
R67 "RC0402JR-070RL" 0402 1873.4,2795.01 r0 bottom value=0
R68 "RC0402JR-070RL" 0402 1873.4,2732.64 r0 bottom value=0
R70 "CRCW04027K87FKED" 0402 2548.48,2954.67 r0 top value=7.87k
R71 "RC0402JR-070RL" 0402 2539.95,2465.78 r0 top value=0
R72 "RC0402JR-070RL" 0402 2565.62,2680.9 r180 top value=0
R73 "RC0402JR-070RL" 0402 3224.77,2475.81 r180 top value=0
R74 "RC0402JR-070RL" 0402 3217.34,2621.55 r0 top value=0
R75 "CRCW040282K5FKED" 0402 2548.83,2897.2 r180 top value=82.5k
R76 "10K" FP-CRCW040210K0FKEDC_0402-MFG 2452.58,2822.81 r180 top value=10k
R77 "CRCW04027K87FKED" 0402 2548.48,2780.11 r0 top value=7.87k
R78 "CRCW040282K5FKED" 0402 2548.48,2838.84 r180 top value=82.5k
S1 "PTS635SL50LFS" SW_PTS635SL50 3289.96,2098.89 r180 top
S2 "PTS635SL50LFS" SW_PTS635SL50 3289.96,2288.15 r180 top
S3 "219-2MST" SW_219-2MST 2865.67,2860.04 r0 top
SH-J1 "J2: 1-2" SNT-100-BK-G 1690.81,2177.82 r90 top value=1x2
SH-J2 "J2: 3-4" SNT-100-BK-G 1790.81,2177.82 r90 top value=1x2
SW1 "418117270901" FP-418117270901_DIP_SW1-MFG 2064.77,1242.23 r270 top
TP1 "TESTPOINT" TP_25MIL-SMT 1458.63,1511.66 r90 top
TP2 "TESTPOINT" TP_25MIL-SMT 2219.57,1422.91 r90 top
U1 "TPD4E004DRYR" DRY0006A 3184.88,1794.97 r0 top
U2 "BQ25616JRTW" RTW0024P 2380.19,683.76 r0 bottom
U3 "TPS63806YFF" YFF0015AHAN 1713.19,1575.4 r270 top
U4 "CC1352R1F3RGZR" RGZ0048A 1074.83,2089.46 r0 top locked
U5 "MX25R8035FZUIL0" FP-MX25R8035FZUIL0_USON8-0 1063.41,1674.64 r0 top
U6 "HDC3020DEF" DEF0008A-MFG 2682.76,2532.09 r0 top
U7 "DRV5032FBDBZT" DBZ0003A_N 3368.24,2810.61 r0 top
U8 "OPT3005DTSR" DTS0008A-MFG 3196.03,2548.3 r0 top
U9 "TLV8544PWR" PW0014A_N 2261.45,2099.53 r180 top
U10 "IRA-S210ST01" Murata_IRA-E700ST0 2798.79,2178.44 r0 top
Y1 "32.768 KHz" Epson_FC-135 778.56,1901.18 r0 top
Y2 "CX2016DB48000C0FPLC1" Kyocera_CX2016DB 959.52,2330.23 r90 top
ZZ1 "This Assembly Note is for PCB labels only" AssemblyNoteLabel -1799.27,-356.4 r0 top
ZZ2 "These assemblies are ESD sensitive, ESD precautions shall be observed." AssemblyNote -1798.36,-439.49 r0 top
ZZ3 "These assemblies must be clean and free from flux and all contaminants. Use of no clean flux is not acceptable." AssemblyNote -1798.04,-517.42 r0 top
ZZ4 "These assemblies must comply with workmanship standards IPC-A-610 Class 2, unless otherwise specified." AssemblyNote -1797.45,-598.19 r0 top
ZZ5 "INDICATION FOR COMPONENTS D* ARE GIVEN AT THEIR CATHODE SIDE." AssemblyNote -1797.45,-681.27 r0 top

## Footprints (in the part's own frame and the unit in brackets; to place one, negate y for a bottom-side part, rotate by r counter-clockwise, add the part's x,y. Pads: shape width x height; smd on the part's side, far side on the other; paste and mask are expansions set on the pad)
0-MFG [mm]
  rrect22% 0.46x0.74 smd paste-1000 mask-1000: 1(-1.93,-3.085)
  rrect14% 1x0.74 smd paste-1000 mask-1000: 2(-5.31,-3.085) 3(-3.11,-3.085)
  Top Layer region: -2.61,-2.715 -12.79,-2.715 -12.79,3.455 12.79,3.455 12.79,2.245 -3.61,2.245 -3.61,0.445 -2.61,0.445 -2.61,-0.325 -1.7,-1.235 -1.7,-2.715 -2.16,-2.715 -2.16,-1.425 -2.82,-0.765 -5.81,-0.765 -5.81,0.445 -4.81,0.445 -4.81,1.245 -10.61,1.245 -10.61,-1.425 -2.61,-1.425 -2.61,-2.715
0201 [mm] "Data from Kemet datasheet CC101_COM dated 7/28/11"
  rect 0.46x0.42 smd mask+0.048: 1(-0.33,0) 2(0.33,0)
  body extent -0.31,-0.16 0.31,0.16, height 0.26
0402 [mm] "0402 from SM-752 data"
  rect 0.8x0.6 smd: 1(-0.6,0) 2(0.6,0)
  silkscreen extent -1.22,-0.52 1.22,0.52, body extent -0.55,-0.3 0.55,0.3, height 0.6
0402L [mm] "0402 from SM-752 data"
  rect 0.6x0.5 smd: 1(-0.5,0) 2(0.5,0)
  body extent -0.55,-0.3 0.55,0.3, height 0.6
0402S [mil] "Based on C0402S footprint from PADS legacy"
  rect 15x24 smd: 1(-20,0) 2(20,0)
  body extent -22,-12 22,12, height 24
0603 [mm] "0603 from SM-752 data"
  rect 1x0.95 smd: 1(-0.8,0) 2(0.8,0)
  silkscreen extent -1.52,-0.69 1.52,0.69, body extent -0.87,-0.47 0.87,0.47, height 1
0603L [mm] "0603 from SM-752 data"
  rect 0.8x0.85 smd: 1(-0.7,0) 2(0.7,0)
  silkscreen extent -0.07,-0.33 0.07,0.33, body extent -0.87,-0.47 0.87,0.47, height 1
0805_HV [mil] "0805 with 30mil clearance between pads"
  rect 50x63 smd: 1(-40,0) 2(40,0)
  silkscreen extent -74,-40 74,40, body extent -43,-29 43,29, height 57
1206 [mm] "1206 from SM-752 data"
  rect 1.3x1.85 smd: 1(-1.45,0) 2(1.45,0)
  silkscreen extent -2.4,-1.21 2.4,1.21, body extent -1.7,-0.9 1.7,0.9, height 1.35
1206_180 [mm] "1206_180"
  rect 1.1x1.6 smd: 1(-1.7,0) 2(1.7,0)
  silkscreen extent -0.9,-1 0.9,1, body extent -1.75,-0.95 1.75,0.95, height 1.8
AssemblyNote [mil] "Assembly Note"
AssemblyNoteLabel [mil] "Assembly Note for PCB Labels"
CE_Mark_5mm [mil] "Minimum text height for CE Mark"
  silkscreen extent -138,-98 138,98
CONN_105017-0001 [mm] "Molex Micro USB-B"
  rect 0.4x1.35 smd: 1(-1.3,1.35) 2(-0.65,1.35) 3(0,1.35) 4(0.65,1.35) 5(1.3,1.35)
  oval 1.2x1.9 hole 0.6 slot 1.3 at 90 deg: 6(-3.5,-1.35) 9(3.5,-1.35)
  rect 1.5x1.9 smd: 7(-1,-1.35) 8(1,-1.35)
  round 1.45 hole 0.85: 10(2.5,1.35) 11(-2.5,1.35)
  Top Layer region: -3.5,-2.3 -2.3,-2.3 -2.3,-0.4 -3.5,-0.4
  Top Layer region: 3.5,-0.4 2.3,-0.4 2.3,-2.3 3.5,-2.3
  silkscreen extent -4.1,-0.2 4.1,1.4, body extent -4.1,-3.93 4.1,1.5, height 2.72
DBZ0003A_N [mm] "SOT23, 3-Leads, Body 2.9x1.3mm, Pitch 0.95mm, Lead Span 2.4mm, IPC Medium Density"
  rrect17% 1x0.6 smd: 1(-1.2,0.95) 2(-1.2,-0.95) 3(1.2,0)
  silkscreen extent 0.2,-1.5 0.7,1.5, body extent -1.26,-1.46 1.26,1.46, height 0.98
DEF0008A-MFG [mm]
  rrect40% 0.6x0.25 smd paste+0 mask+0: 1(-1.15,0.75) 2(-1.15,0.25) 3(-1.15,-0.25) 4(-1.15,-0.75) 5(1.15,-0.75) 6(1.15,-0.25) 7(1.15,0.25) 8(1.15,0.75)
  rrect8% 1.2x1.9 smd paste-1000 mask+0: 9(0,0)
  silkscreen extent -2.15,-1.3 1.3,1.3, body extent -1.55,-1.4 1.55,1.4, height 0.25
DQK0006C [mm] "WSON"
  rrect12% 0.9x0.86 on Bottom Paste: 0(0,0.325)
  rrect34% 0.7x0.29 on Bottom Paste: 0(0.095,-0.65)
  rrect33% 0.45x0.3 smd: 1(-0.975,0.65) 2(-0.975,0) 3(-0.975,-0.65) 4(0.975,-0.65) 5(0.975,0) 6(0.975,0.65)
  rrect33% 0.75x0.3 smd paste-0.15: 7(0.095,-0.65)
  rrect11% 1x0.95 smd paste-0.5: 8(0,0.325)
  silkscreen extent -1.15,-1.15 1.15,1.15, body extent -1,-1 1,1, height 0.82
DRY0006A [mm] "USON-6"
  rrect67% 0.45x0.3 smd paste-0.05 mask-0.05: 1(-0.275,0.5)
  rrect67% 0.4x0.3 smd paste-0.05 mask-0.05: 2(-0.3,0) 3(-0.3,-0.5) 4(0.3,-0.5) 5(0.3,0) 6(0.3,0.5)
  body extent -0.5,-0.72 0.5,0.73, height 0.58
DTS0008A-MFG [mm]
  rrect33% 0.72x0.3 smd paste+0 mask+0: 1(-0.86,0.75) 2(-0.86,0.25) 3(-0.86,-0.25) 4(-0.86,-0.75) 5(0.86,-0.75) 6(0.86,-0.25) 7(0.86,0.25) 8(0.86,0.75)
  silkscreen extent -1.97,-1.1 0.13,1.1, body extent -1.32,-1.35 1.32,1.35, height 0.25
Epson_FC-135 [mm] "SMD, 2-Leads, Body 3.2x1.5mm"
  rect 1x1.8 smd: 1(-1.25,0) 2(1.25,0)
  silkscreen extent -0.35,-0.8 0.35,0.8, body extent -1.65,-0.8 1.65,0.8, height 0.9
FCC_disclaimer [mil]
Fiducial10-20 [mm]
  round 1 smd mask+0.5: 1(0,0)
  Top Layer keep-out circle w1.178: c0,0 r0.5
FP-851-43-008-10-021000_HDR8-MFG [mm]
  rrect9% 1.12x1.12 hole 0.7 paste-2539.97 mask+0: 1(-4.445,0)
  round 1.12 hole 0.7 paste-2539.97 mask+0: 2(-3.175,0) 3(-1.905,0) 4(-0.635,0) 5(0.635,0) 6(1.905,0) 7(3.175,0) 8(4.445,0)
  silkscreen extent -6,-1.17 5.27,1.17, body extent -5.37,-1.27 5.37,1.27, height 0.25
FP-0900PC15A0036_0805-MFG [mm]
  rrect48% 0.25x0.8 smd paste+0 mask+0: 1(-0.75,-0.78) 2(-0.25,-0.78) 3(0.25,-0.78) 4(0.75,-0.78) 6(0.75,0.78) 7(0.25,0.78) 8(-0.25,0.78) 9(-0.75,0.78)
  rrect51% 0.8x0.35 smd paste+0 mask+0: 5(1.155,0) 10(-1.155,0)
  silkscreen extent -1.95,-1.88 1.95,0.72, body extent -1.66,-1.28 1.66,1.28, height 0.25
FP-1043P_BATT_HOLDER_18650-MFG [mm]
  rrect5% 2.02x2.02 hole 1.32 paste-2539.97 mask+0: 1(-36.11,0)
  round 2.02 hole 1.32 paste-2539.97 mask+0: 2(36.11,0)
  round 3.55 hole 3.55 unplated paste-2539.97 mask+0: ""(-27.6,-8) ""(27.6,8)
  round 2.39 hole 2.39 unplated paste-2539.97 mask+0: ""(35.8,-8)
  silkscreen extent -39.95,-10.45 39.95,10.45, body extent -38.75,-10.55 38.75,10.55, height 0.25
"FP-1909763-1_SMT_JACK _CONN-MFG" [mm]
  rrect10% 1x1.05 smd paste+0 mask+0: 1(0,-1.6)
  rrect10% 1.05x2.2 smd paste+0 mask+0: 2(-1.475,-0.075) 3(1.475,-0.075)
  silkscreen extent -1.43,-2.8 1.43,1.5, body extent -2.1,-2.22 2.1,1.6, height 0.25
FP-0732511150_CONN_RF_JACK-MFG [mil]
  rect 229.92x90.16 smd paste+0 mask+0: 1(209,0)
  round 85.57 smd paste+0 mask+0: 2(209,172.54) 3(209,-172.54)
  round 85.57 smd far side paste+0 mask+0: 4(209,172.54) 5(209,-172.54)
  Top Layer region: 94.04,-220.08 323.96,-220.08 323.96,-125 94.04,-125 94.04,-135.04 121.99,-135.04 121.99,-192.52 94.04,-192.52
  Top Layer region: 94.04,220.08 323.96,220.08 323.96,125 94.04,125 94.04,135.04 121.99,135.04 121.99,192.52 94.04,192.52
  Bottom Layer region: 94.04,-220.08 323.96,-220.08 323.96,-125 94.04,-125 94.04,-135.04 121.99,-135.04 121.99,-192.52 94.04,-192.52
  Bottom Layer region: 94.04,220.08 323.96,220.08 323.96,125 94.04,125 94.04,135.04 121.99,135.04 121.99,192.52 94.04,192.52
  silkscreen extent 288,-110 351,110, body extent -291,-224 328,224, height 10
FP-418117270901_DIP_SW1-MFG [mm]
  rrect8% 1.3x1.3 hole 0.8 paste-2539.97 mask+0: 1(0,-3.81)
  round 1.3 hole 0.8 paste-2539.97 mask+0: 2(0,3.81)
  silkscreen extent -2.02,-5.62 2.02,5, body extent -2.12,-5.1 2.12,5.1, height 0.25
FP-BLM18KG121TN1D_0603-MFG [mm]
  rrect15% 0.65x0.7 smd paste+0 mask+0: 1(-0.675,0) 2(0.675,0)
  silkscreen extent -0.87,-0.8 0.87,0.8, body extent -1.1,-0.58 1.1,0.58, height 0.25
FP-BLM21PG300SN1D_0805-MFG [mm]
  rrect17% 0.6x1.2 smd paste-1000 mask-1000: 1(-0.9,0) 2(0.9,0)
  silkscreen extent -0.23,-0.72 0.23,0.72, body extent -1.3,-0.82 1.3,0.82, height 0.25
FP-CRCW040210K0FKEDC_0402-MFG [mm]
  rrect25% 0.4x0.6 smd paste+0 mask+0: 1(-0.45,0) 2(0.45,0)
  silkscreen extent -0.55,-0.67 0.55,0.67, body extent -0.75,-0.4 0.75,0.4, height 0.25
FP-GRM033R60J104KE19D_0201-MFG [mm]
  rrect40% 0.25x0.3 smd paste+0 mask+0: 1(-0.238,0) 2(0.238,0)
  silkscreen extent -0.32,-0.53 0.32,0.53, body extent -0.46,-0.27 0.46,0.27, height 0.25
FP-GRM033R61E102KA01D_0201-MFG [mm]
  rrect40% 0.25x0.3 smd paste+0 mask+0: 1(-0.238,0) 2(0.238,0)
  silkscreen extent -0.32,-0.54 0.32,0.54, body extent -0.3,-0.15 0.3,0.15, height 0.33
FP-GRM188R61C475KE11D_0603-MFG [mm]
  rrect13% 0.75x0.9 smd paste+0 mask+0: 1(-0.775,0) 2(0.775,0)
  silkscreen extent -0.8,-0.8 0.8,0.8, body extent -0.8,-0.4 0.8,0.4, height 0.95
FP-GRM0335C1H1R2BA01D_0201-MFG [mm]
  rrect36% 0.275x0.3 smd paste+0 mask+0: 1(-0.262,0) 2(0.262,0)
  body extent -0.5,-0.27 0.5,0.26, height 0.25
FP-MX25R8035FZUIL0_USON8-0 [mm]
  rrect40% 0.3x0.25 smd paste+0 mask+0: 1(-1.2,0.75) 2(-1.2,0.25) 3(-1.2,-0.25) 4(-1.2,-0.75) 5(1.2,-0.75) 6(1.2,-0.25) 7(1.2,0.25) 8(1.2,0.75)
  rrect50% 0.2x1.6 smd paste+0 mask+0: 9(0,0)
  body extent -1.65,-1.15 1.65,1.15, height 0.25
FP-RC0402JR-07100KL_0402-MFG [mm]
  rrect20% 0.5x0.6 smd paste+0 mask+0: 1(-0.5,0) 2(0.5,0)
  silkscreen extent -0.5,-0.67 0.5,0.67, body extent -0.85,-0.4 0.85,0.4, height 0.25
FP-RC0402JR-13100RL_0402-MFG [mm]
  rrect20% 0.5x0.6 smd paste+0 mask+0: 1(-0.5,0) 2(0.5,0)
  silkscreen extent -0.5,-0.67 0.5,0.67, body extent -0.5,-0.25 0.5,0.25, height 0.4
FP-VLMY1500-GS08_0402-MFG [mm]
  rrect17% 0.6x0.7 smd paste+0 mask+0: 1(-0.475,0) 2(0.475,0)
  silkscreen extent -1.45,-0.72 0.6,0.72, body extent -0.87,-0.45 0.87,0.45, height 0.25
G563EGBW [mm] "PLCC, 6-Leads, Body 5x5mm, Pitch 1.6mm"
  rrect8% 1.3x1.3 smd: 1(-2.25,1.6) 2(-2.25,0) 3(-2.25,-1.6) 4(2.25,-1.6) 5(2.25,0) 6(2.25,1.6)
  body extent -2.6,-2.6 2.6,2.6, height 1.8
Keystone_1051 [mm] "TH, 2-Leads, Body 42.93x18.29mm, Height 15.49mm"
  rect 1.7x1.7 hole 1.19: 1(-18.91,0)
  round 1.7 hole 1.19: 2(18.91,0)
  round 0 hole 1.98 unplated: MH(-18.91,8.1)
  silkscreen extent -23.81,-9.27 23.81,9.27, body extent -21.46,-9.27 21.46,9.27, height 15.49
Kyocera_CX2016DB [mm] "SMD, 4-Leads, Body 2x1.6mm"
  rrect12% 0.8x0.9 smd: 1(-0.55,0.7) 2(-0.55,-0.7) 3(0.55,-0.7) 4(0.55,0.7)
  silkscreen extent -1.5,0.6 -1.3,0.8, body extent -0.85,-1.05 0.85,1.05, height 0.45
LED_LTST-C190 [mm] "Lite-On"
  rect 0.8x0.8 smd: 1(-0.75,0) 2(0.75,0)
  silkscreen extent -1.1,-0.8 1.8,0.8, body extent -0.85,-0.45 0.85,0.45, height 0.9
Murata_IRA-E700ST0 [mm] "TH, 3-Leads, Dia 9.2mm"
  rect 1.25x1.25 hole 0.75: 1(-1.796,-1.796)
  round 1.25 hole 0.75: 2(1.796,-1.796) 3(1.796,1.796)
  silkscreen extent -5.5,-4.7 4.7,4.7, body extent -5.5,-4.7 4.7,4.7, height 4.9
NPTH125mil [mil]
  round 120 hole 125 unplated mask+15: 1(0,0)
PhoenixConact_1727010 [mm]
  rect 1.7x1.7 hole 1.1: 1(-1.905,0)
  round 1.7 hole 1.1: 2(1.905,0)
  silkscreen extent -4.8,-3.6 3.81,3.6, body extent -3.81,-3.6 3.81,3.7, height 8.52
PRECI-DIP_851-87-005-10-001101 [mm] "PRECI-DIP"
  rect 1.05x1.05 hole 0.7: 1(-2.54,0)
  round 1.05 hole 0.7: 2(-1.27,0) 3(0,0) 4(1.27,0) 5(2.54,0)
  silkscreen extent -4.14,-1.1 3.38,1.1, body extent -3.38,-1.1 3.38,1.1, height 4.1
PW0014A_N [mm] "TSOP, 14-Leads, Body 5x4.4mm, Pitch 0.65mm, IPC Medium Density"
  oval 1.4x0.45 smd: 1(-2.95,1.95) 2(-2.95,1.3) 3(-2.95,0.65) 4(-2.95,0) 5(-2.95,-0.65) 6(-2.95,-1.3) 7(-2.95,-1.95) 8(2.95,-1.95) 9(2.95,-1.3) 10(2.95,-0.65) 11(2.95,0) 12(2.95,0.65) 13(2.95,1.3) 14(2.95,1.95)
  silkscreen extent -3.4,-2.55 1.85,2.55, body extent -3.21,-2.5 3.21,2.5, height 1
RC0402 [mm] "SMD, 2-Leads, Body 1x0.5mm"
  rrect20% 0.5x0.6 smd: 1(-0.5,0) 2(0.5,0)
  body extent -0.53,-0.28 0.53,0.28, height 0.4
RGZ0048A [mm] "VQFN-48"
  rrect42% 0.6x0.24 smd: 1(-3.4,2.75) 2(-3.4,2.25) 3(-3.4,1.75) 4(-3.4,1.25) 5(-3.4,0.75) 6(-3.4,0.25) 7(-3.4,-0.25) 8(-3.4,-0.75) 9(-3.4,-1.25) 10(-3.4,-1.75) 11(-3.4,-2.25) 12(-3.4,-2.75) 25(3.4,-2.75) 26(3.4,-2.25) 27(3.4,-1.75) 28(3.4,-1.25) 29(3.4,-0.75) 30(3.4,-0.25) 31(3.4,0.25) 32(3.4,0.75) 33(3.4,1.25) 34(3.4,1.75) 35(3.4,2.25) 36(3.4,2.75)
  rrect42% 0.24x0.6 smd: 13(-2.75,-3.4) 14(-2.25,-3.4) 15(-1.75,-3.4) 16(-1.25,-3.4) 17(-0.75,-3.4) 18(-0.25,-3.4) 19(0.25,-3.4) 20(0.75,-3.4) 21(1.25,-3.4) 22(1.75,-3.4) 23(2.25,-3.4) 24(2.75,-3.4) 37(2.75,3.4) 38(2.25,3.4) 39(1.75,3.4) 40(1.25,3.4) 41(0.75,3.4) 42(0.25,3.4) 43(-0.25,3.4) 44(-0.75,3.4) 45(-1.25,3.4) 46(-1.75,3.4) 47(-2.25,3.4) 48(-2.75,3.4)
  rrect2% 5.15x5.15 smd paste-2.6: 49(0,0)
  body extent -3.5,-3.5 3.5,3.5, height 1
RTW0024P [mm] "PVQFN-24"
  rrect36% 0.85x0.28 smd paste-0.28: 1(-1.975,1.25) 2(-1.975,0.75) 3(-1.975,0.25) 4(-1.975,-0.25) 5(-1.975,-0.75) 6(-1.975,-1.25) 13(1.975,-1.25) 14(1.975,-0.75) 15(1.975,-0.25) 16(1.975,0.25) 17(1.975,0.75) 18(1.975,1.25)
  rrect36% 0.28x0.85 smd paste-0.28: 7(-1.25,-1.975) 8(-0.75,-1.975) 9(-0.25,-1.975) 10(0.25,-1.975) 11(0.75,-1.975) 12(1.25,-1.975) 19(1.25,1.975) 20(0.75,1.975) 21(0.25,1.975) 22(-0.25,1.975) 23(-0.75,1.975) 24(-1.25,1.975)
  rrect4% 2.7x2.7 smd paste-2.7: 25(0,0)
  body extent -2.07,-2.07 2.07,2.07, height 0.8
Samtec_FTSH-105-01-x-DV-K [mm] "Header(Shrouded), 1.27mm, 5x2, SMT"
  rect 2.79x0.74 smd: 1(-2.035,2.54) 2(2.035,2.54) 3(-2.035,1.27) 4(2.035,1.27) 5(-2.035,0) 6(2.035,0) 7(-2.035,-1.27) 8(2.035,-1.27) 9(-2.035,-2.54) 10(2.035,-2.54)
  silkscreen extent -3.73,-3.48 3.73,3.48, body extent -2.92,-3.18 2.92,3.17, height 6.13
SMB [mil] "Molded Diode, 2-Leads, Body 5.4x3.6mm, IPC Medium Density, based on OnSemi component dimensions"
  rect 85x107.99 smd: 1(-87.01,0) 2(87.01,0)
  silkscreen extent -155,-82 125,82, body extent -106,-71 106,71, height 91
SNT-100-BK-G [mil] "Samtec STEP model"
  round 1 on Mech3: 0(0,0)
  body extent -100,-50 100,50, height 344
SOD-128 [mm] "SMD, 2-Leads, Body 4x2.7mm, Height 1.1mm"
  rect 1.4x2.1 smd paste-0.1: 1(-2.2,0) 2(2.2,0)
  silkscreen extent -3.45,-1.45 2.95,1.45, body extent -2.5,-1.35 2.5,1.35, height 1.11
SOD-523 [mm] "NXP Semiconductor recommended land pattern, nominal STEP model"
  rect 0.8x0.6 smd paste-0.05: 1(-0.55,0) 2(0.55,0)
  silkscreen extent -1.65,-0.66 1.2,0.66, body extent -0.8,-0.4 0.8,0.4, height 0.72
SOT-23 [mm] "SOT23, 3-Leads, Body 2.9x1.3mm, Pitch 0.95mm, Lead Span 2.5mm, IPC Medium Density"
  rrect50% 1x0.6 smd: 1(-1.2,0.95) 2(-1.2,-0.95) 3(1.2,0)
  silkscreen extent -1.63,-1.5 0.7,1.5, body extent -1.16,-1.45 1.21,1.45, height 1
SOT-323 [mm] "Diodes Inc recommended land pattern.  2016-02-24"
  rrect21% 0.6x0.47 smd: 1(-0.95,0.65) 2(-0.95,-0.65) 3(0.95,0)
  silkscreen extent -1.14,-1.22 0.77,1.22, body extent -1.13,-1.13 1.12,1.12, height 1.13
Sullins_LPPB122CFFN [mm] "Receptacle, 1.27mm, 12x2, TH"
  rrect50% 1x1 hole 0.6: 1(-6.985,0.635)
  round 1 hole 0.6: 2(-6.985,-0.635) 3(-5.715,0.635) 4(-5.715,-0.635) 5(-4.445,0.635) 6(-4.445,-0.635) 7(-3.175,0.635) 8(-3.175,-0.635) 9(-1.905,0.635) 10(-1.905,-0.635) 11(-0.635,0.635) 12(-0.635,-0.635) 13(0.635,0.635) 14(0.635,-0.635) 15(1.905,0.635) 16(1.905,-0.635) 17(3.175,0.635) 18(3.175,-0.635) 19(4.445,0.635) 20(4.445,-0.635) 21(5.715,0.635) 22(5.715,-0.635) 23(6.985,0.635) 24(6.985,-0.635)
  silkscreen extent -7.92,-1.65 7.92,2, body extent -7.82,-1.55 7.82,1.55, height 4.5
SW_219-2MST [mm] "SMT, 4-Leads, Body 6.55x6.7mm, Pitch 2.54mm"
  rect 2.44x1.13 smd: 1(-4.3,1.27) 2(-4.3,-1.27) 3(4.3,-1.27) 4(4.3,1.27)
  silkscreen extent -3.7,-3.28 3.35,3.38, body extent -4.95,-3.28 4.95,3.28, height 4.32
SW_PTS635SL50 [mm] "C&K"
  rect 2x2 hole 1.3: 1(-3.25,0)
  round 2 hole 1.3: 2(3.25,0)
  silkscreen extent -3.22,-1.95 3.22,1.95, body extent -3.25,-1.75 3.25,1.75, height 5
TI_Stacked_Overlay_Small [mil]
  silkscreen extent -418,-98 418,98
TP_25MIL-SMT [mil]
  round 25 smd mask-2.5: 1(0,0)
TSW-102-07-G-S [mm] "Samtec 100mil, 1x2, 230 mil above insulator"
  rrect50% 1.65x1.65 hole 1.016: 1(-1.27,0)
  round 1.65 hole 1.016: 2(1.27,0)
  silkscreen extent -3.17,-1.27 2.54,1.27, body extent -2.54,-1.27 2.54,1.27, height 8.38
TSW-103-07-G-D [mm] "Samtec 100mil, 2x3, 230 mil above insulator"
  rect 1.65x1.65 hole 1.016: 1(-2.54,-1.27)
  round 1.65 hole 1.016: 2(-2.54,1.27) 3(0,-1.27) 4(0,1.27) 5(2.54,-1.27) 6(2.54,1.27)
  silkscreen extent -4.83,-2.54 3.81,2.54, body extent -3.81,-2.54 3.81,2.54, height 8.38
TSW-104-07-G-S [mm] "Samtec 100mil, 1x4, 230 mil above insulator"
  rrect50% 1.65x1.65 hole 1.016: 1(-3.81,0)
  round 1.65 hole 1.016: 2(-1.27,0) 3(1.27,0) 4(3.81,0)
  body extent -5.08,-1.27 5.08,1.27, height 8.38
WE-SPC_4838 [mm] "WURTH"
  rect 2x5.3 smd: 1(-1.75,0) 2(1.75,0)
  silkscreen extent -0.48,-2.65 0.48,2.65, body extent -2.55,-2.55 2.55,2.55, height 4.1
WEEE_Minimum [mil] "WEEElie bin"
  silkscreen extent -95,-172 99,104
XFL4015 [mm] "SMD, 2-Leads, Body 4x4mm"
  rect 0.98x3.4 smd: 1(-1.185,0) 2(1.185,0)
  silkscreen extent -2.15,-2.15 2.15,2.15, body extent -2.15,-2.15 2.15,2.15, height 1.6
YFF0015AHAN [mm] "DSBGA, 15-Leads, Body 2.3x1.375mm, Pitch 0.4mm"
  round 0.23 smd paste-0.13 mask+0.038: A1(-0.4,0.8) A2(0,0.8) A3(0.4,0.8) B1(-0.4,0.4) B2(0,0.4) B3(0.4,0.4) C1(-0.4,0) C2(0,0) C3(0.4,0) D1(-0.4,-0.4) D2(0,-0.4) D3(0.4,-0.4) E1(-0.4,-0.8) E2(0,-0.8) E3(0.4,-0.8)
  silkscreen extent -0.78,-1.23 0.77,1.23, body extent -0.69,-1.15 0.69,1.15, height 0.63

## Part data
ANT1: library part CMP-0091830-1, "2.4-GHz Inverted F Antenna", Manufacturer="Texas Instruments", Operating Temperature Range=to
BT2: library part CMP-0003704-1, "Battery Holder, CR123A, TH", Manufacturer=Keystone, Supplier Part Number 1=36-1051-ND
C1 C2 C12 C43 C44: library part CMP-0007497-5, "CAP, CERM, 10 uF, 10 V, +/- 20%, X7R, 0603", Cap_Case=0603, Manufacturer=MuRata, Supplier Part Number 1=81-GRM188Z71A106MA3D, TempCo=X7R, Tolerance_%=20%, Value1=Unknown, Value2=10V, ValueDisplayed=10uF
C3: library part CMP-0006669-2, "CAP, CERM, 0.047 uF, 25 V, +/- 10%, X7R, 0402", Cap_Case=0402, Manufacturer=MuRata, Supplier Part Number 1=490-3254-1-ND, TempCo=X7R, Tolerance_%=10%, Value1=Unknown, Value2=25V, ValueDisplayed=0.047uF
C4 C11 C50: library part CMP-0081849-1, "CAP, CERM, 10 µF,  V,+/- 10%, X7R, 0805", Cap_Case=0805, Manufacturer=MuRata, Supplier Part Number 1=490-10516-2-ND, TempCo=X7R, Tolerance_%=10%, ValueDisplayed=10µF
C5 C9 C10 C45: library part CMP-0008302-2, "CAP, CERM, 10 uF, 25 V, +/- 10%, X5R, 0805", Cap_Case=0805, Manufacturer=MuRata, Supplier Part Number 1=490-5523-1-ND, TempCo=X5R, Tolerance_%=10%, Value1=Unknown, Value2=25V, ValueDisplayed=10uF
C6: library part CMP-0007052-4, "CAP, CERM, 1 uF, 35 V, +/- 10%, X7R, 0603", Cap_Case=0603, Manufacturer=TDK, Supplier Part Number 1=445-7414-1-ND, TempCo=X7R, Tolerance_%=10%, Value1=Unknown, Value2=35V, ValueDisplayed=1uF
C7: library part CMP-0008944-2, "CAP, CERM, 47 uF, 10 V, +/- 10%, X5R, 1206", Cap_Case=1206, Manufacturer=MuRata, Supplier Part Number 1=81-GRM31CR61A476KE5L, TempCo=X5R, Tolerance_%=10%, Value1=Unknown, Value2=10V, ValueDisplayed=47uF
C8: library part CMP-0098153-1, "Chip Multilayer Ceramic Capacitors for General Purpose, 0603, 4.7uF, X5R, 15%, 10%, 16V", Manufacturer=Murata, Operating Temperature Range="-55°C to +85°C", TempCo=15%, Temperature Characteristic=X5R, Tolerance_%=10%, ValueDisplayed=4.7uF
C13: library part CMP-0007398-4, "CAP, CERM, 0.47 uF, 16 V, +/- 10%, X7R, 0603", Cap_Case=0603, Manufacturer=MuRata, Supplier Part Number 1=490-3295-1-ND, TempCo=X7R, Tolerance_%=10%, Value1=Unknown, Value2=16V, ValueDisplayed=0.47uF
C14: library part CMP-0006470-2, "CAP, CERM, 470 pF, 50 V, +/- 5%, C0G/NP0, 0402", Cap_Case=0402, Manufacturer=MuRata, Supplier Part Number 1=490-1297-1-ND, TempCo=C0G/NP0, Tolerance_%=5%, Value1=Unknown, Value2=50V, ValueDisplayed=470pF
C15 C16 C17: library part CMP-0007313-5, "CAP, CERM, 47 uF, 6.3 V, +/- 20%, X5R, 0603", Cap_Case=0603, Manufacturer=MuRata, TempCo=X5R, Tolerance_%=20%, Value1=Unknown, Value2=6.3V, ValueDisplayed=47uF
C18 C19 C20 C21 C22 C24 C25 C32 C38 C39 C40 C41 C48 C57: library part CMP-0006659-2, "CAP, CERM, 0.1 uF, 25 V, +/- 10%, X7R, 0402", Cap_Case=0402, Manufacturer=MuRata, Supplier Part Number 1=490-10698-1-ND, TempCo=X7R, Tolerance_%=10%, Value1=Unknown, Value2=25V, ValueDisplayed=0.1uF
C23: library part CMP-0007306-5, "CAP, CERM, 22 uF, 6.3 V, +/- 20%, X5R, 0603", Cap_Case=0603, Manufacturer=MuRata, Supplier Part Number 1=490-7611-1-ND, TempCo=X5R, Tolerance_%=20%, Value1=Unknown, Value2=6.3V, ValueDisplayed=22uF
